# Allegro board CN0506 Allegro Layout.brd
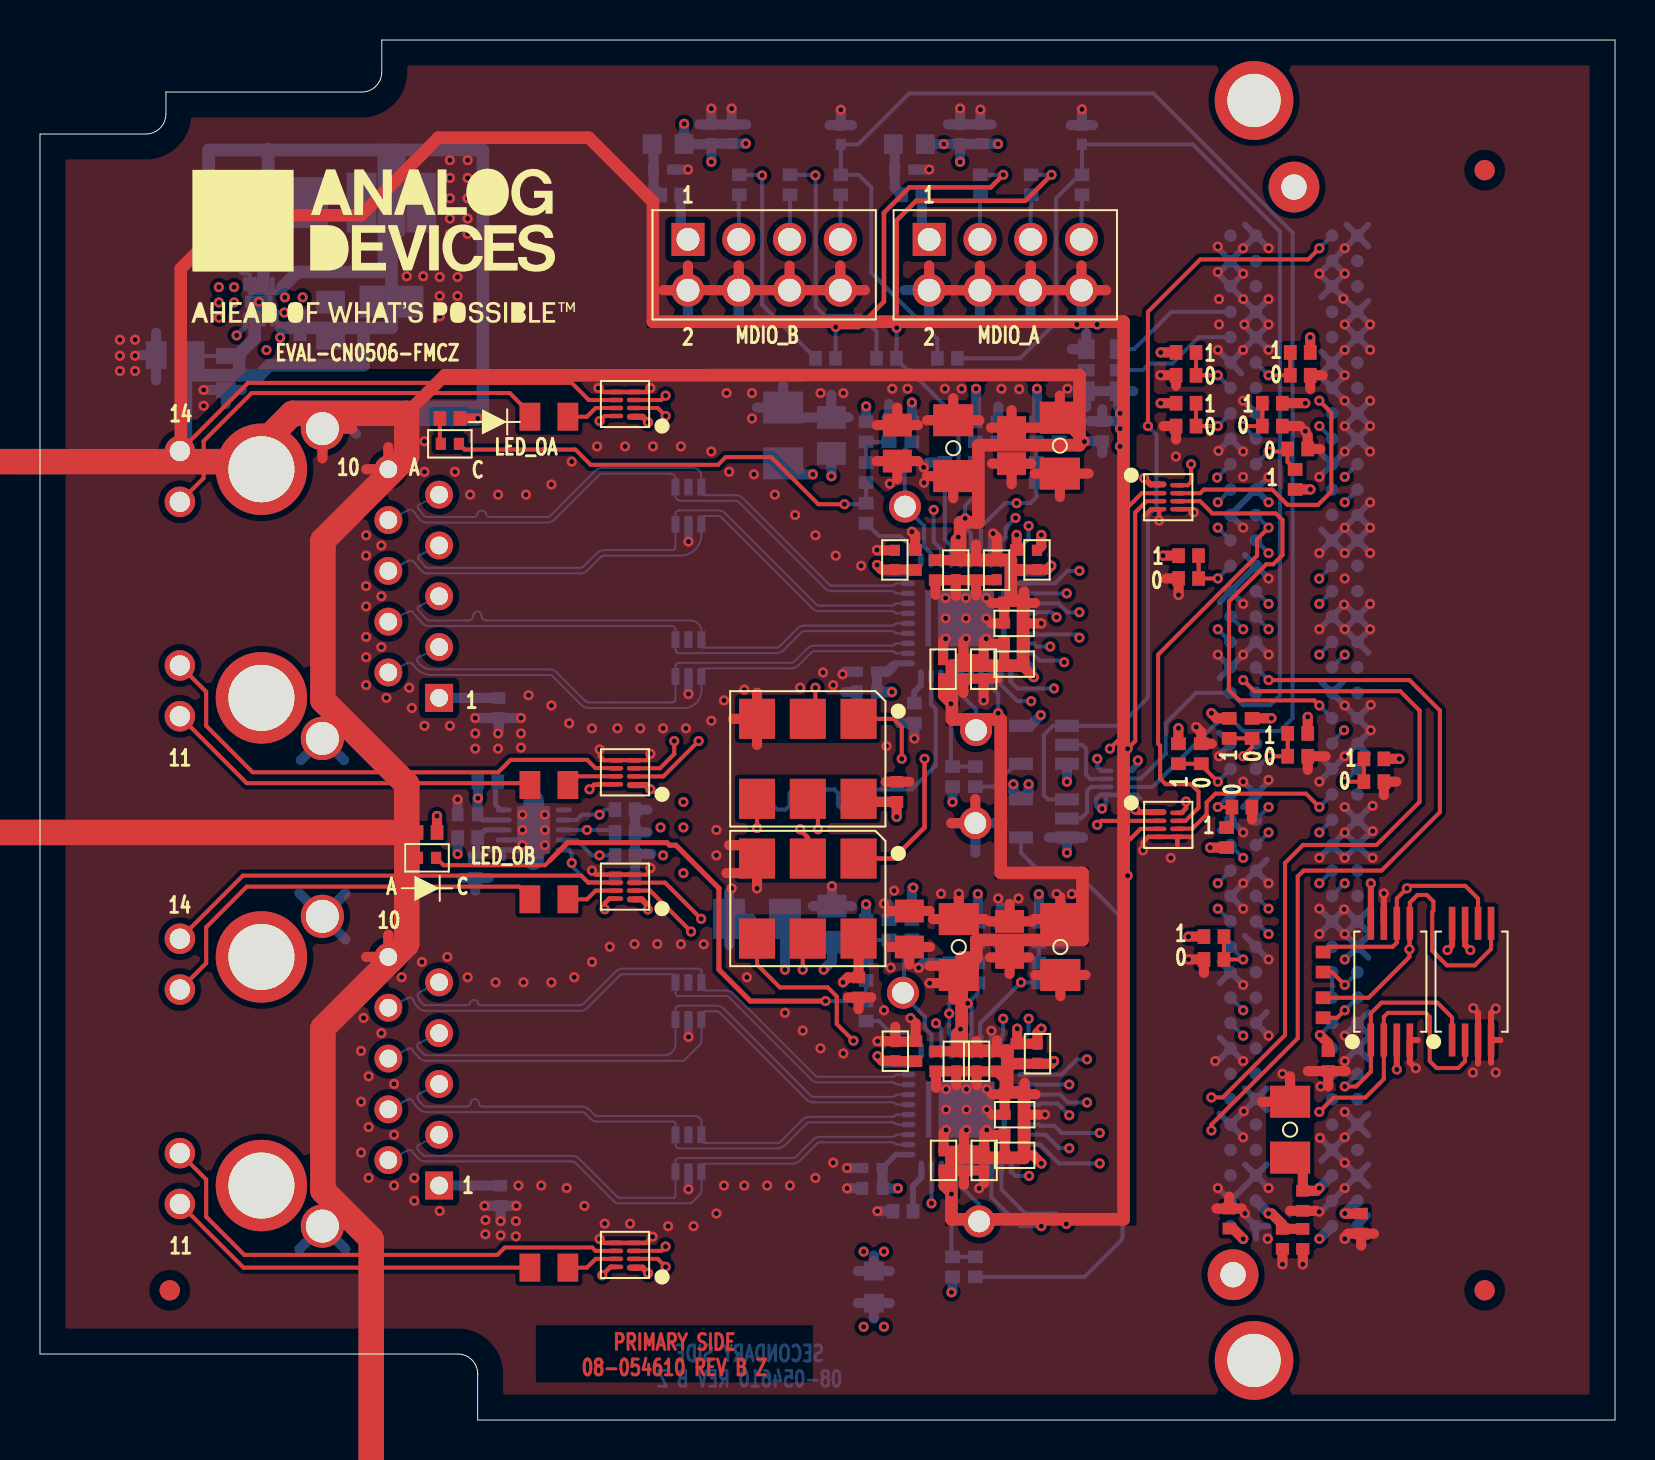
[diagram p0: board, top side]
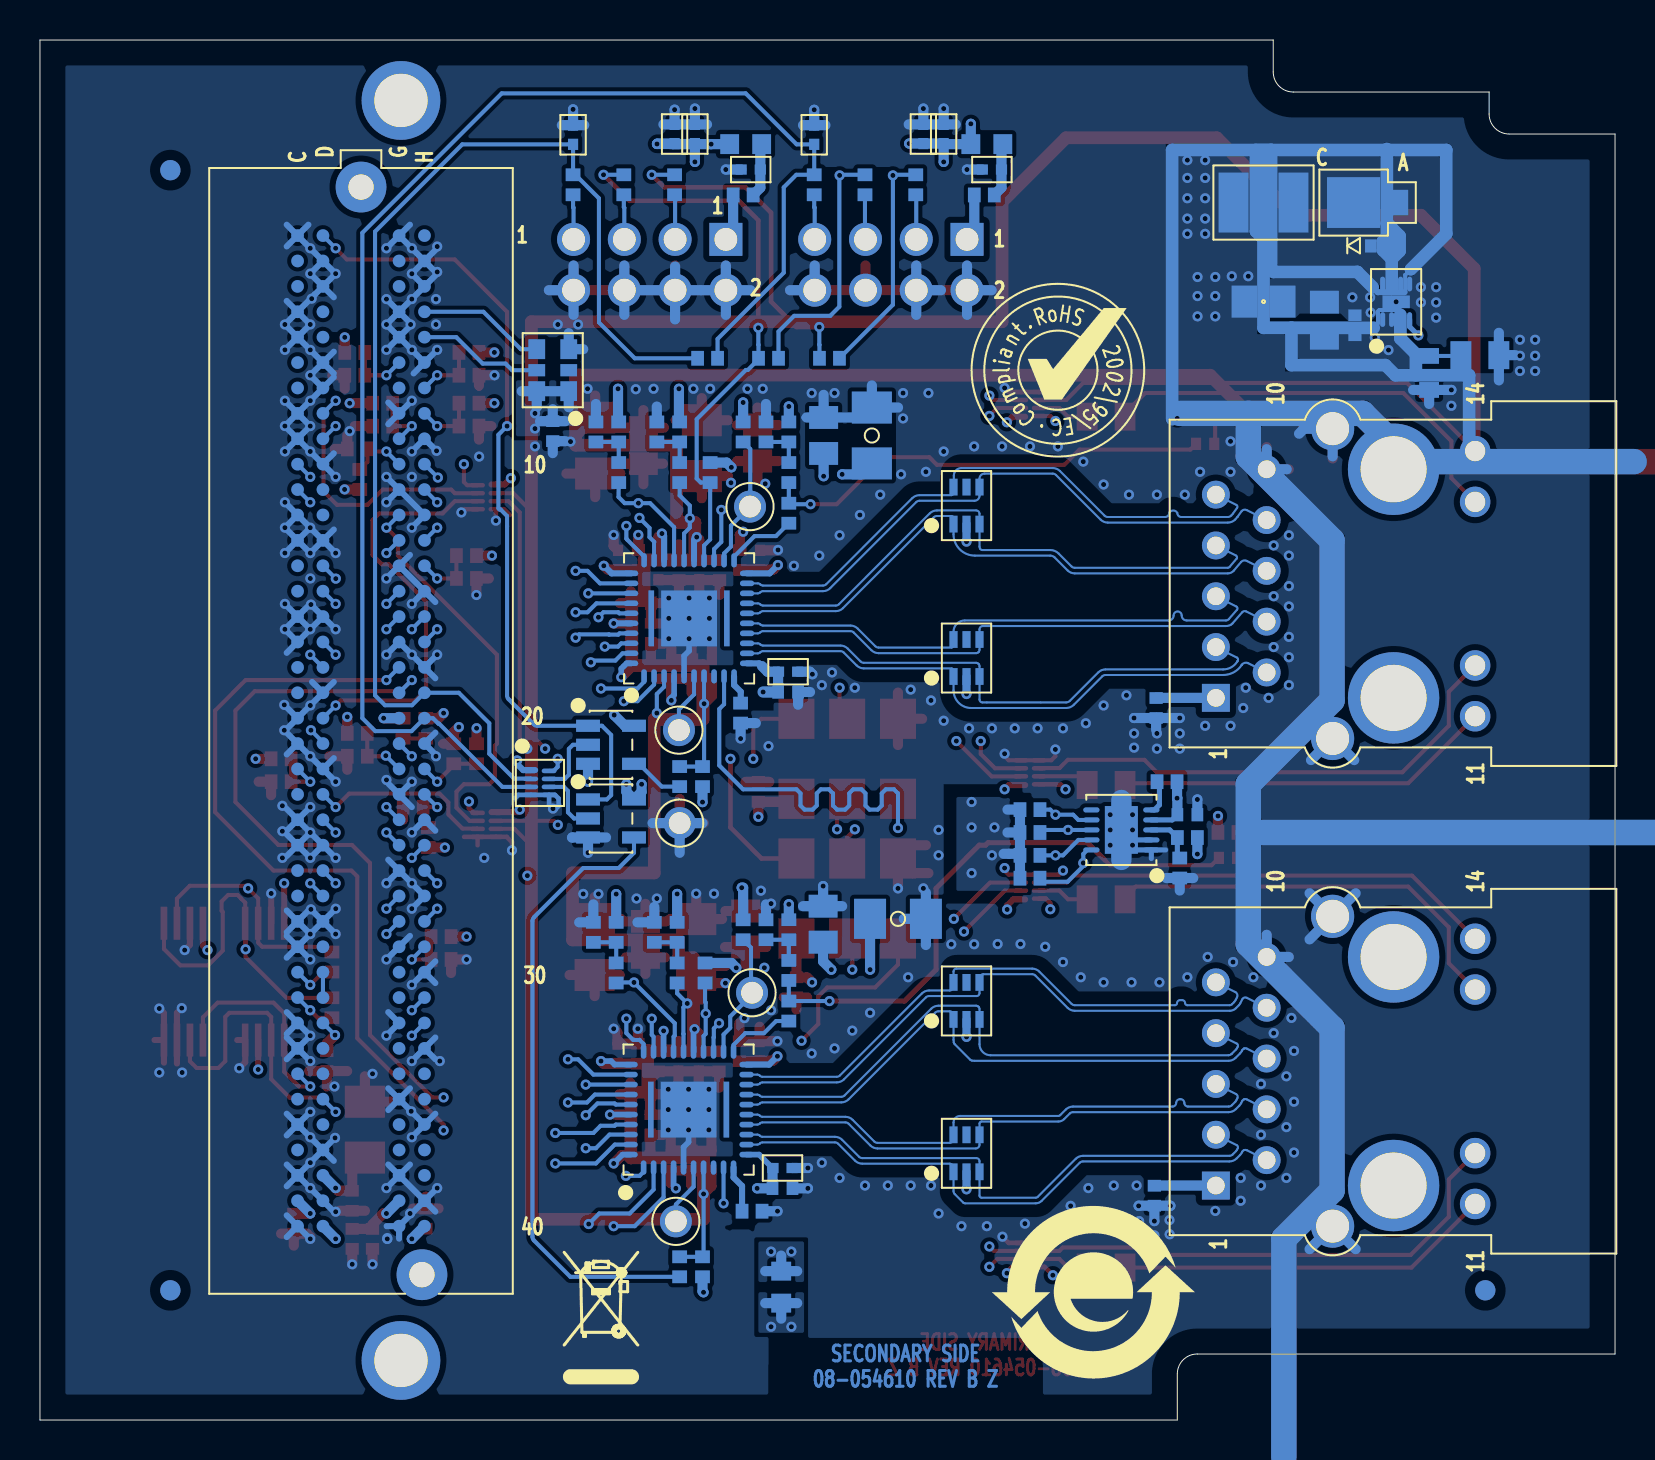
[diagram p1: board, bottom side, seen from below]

Outline 78.8 x 69 mm; copper layers: TOP, L2_GND, L3_SIG, L4_GND, L5_PWR, L6_SIG, L7_GND, BOTTOM. Coordinates in mm from the lower left corner of the outline.
Outline path: 0,64.3 0,3.3 20.9,3.3 arc(21.61,3.01) 21.9,2.3 21.9,0 78.8,0 78.8,69 17.1,69 17.1,67.4 arc(16.81,66.69) 16.1,66.4 6.3,66.4 6.3,65.3 arc(6.01,64.59) 5.3,64.3 0,64.3

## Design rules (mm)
constraint set DEFAULT: min track width 0.203
net group MDI_0A: nets MDI_0A_N MDI_0A_P
net group MDI_0B: nets MDI_0B_N MDI_0B_P
net group MDI_1A: nets MDI_1A_N MDI_1A_P
net group MDI_1B: nets MDI_1B_N MDI_1B_P
net group MDI_2A: nets MDI_2A_N MDI_2A_P
net group MDI_2B: nets MDI_2B_N MDI_2B_P
net group MDI_3A: nets MDI_3A_N MDI_3A_P
net group MDI_3B: nets MDI_3B_N MDI_3B_P
net group XTAL: nets XTAL_I_A XTAL_I_B
net group RX_A: nets RX_CTL/RX_DV_A RXC/RX_CLK_A RXD_0A RXD_1A RXD_2A RXD_3A
net group RX_B: nets RX_CTL/RX_DV_B RXC/RX_CLK_B RXD_0B RXD_1B RXD_2B RXD_3B
net group TX_A: nets TX_CTL/TX_EN_A TXC/TX_CLK_A TXD_0A TXD_1A TXD_2A TXD_3A
net group TX_B: nets TX_CTL/TX_EN_B TXC/TX_CLK_B TXD_0B TXD_1B TXD_2B TXD_3B

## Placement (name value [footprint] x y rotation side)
C1  0.1UF  [C0402]  46.2 37.54 90 top
C2  0.01UF  [C0402H22]  47.21 37.54 90 top
C3  0.01UF  [C0402H22]  45.18 37.54 90 top
C4  0.01UF  [C0402H22]  49.88 43 90 top
C5  0.1UF  [C0402]  48.86 43 90 top
C6  0.1UF  [C0402]  41.37 36.4 180 bottom
C7  0.01UF  [C0402H22]  41.37 37.42 180 bottom
C8  0.1UF  [C0402]  43.78 43 90 top
C9  0.01UF  [C0402H22]  42.77 43 90 top
C10  0.1UF  [C0402]  48.74 40.84 180 top
C11  0.01UF  [C0402H22]  48.74 39.83 180 top
C12  0.1UF  [C0402]  44.8 42.5 270 top
C13  0.01UF  [C0402H22]  48.74 37.8 180 top
C14  1uF  [C0805]  48.61 48.72 90 top
C15  4.7uF  [C1206H71]  51.02 48.72 270 top
C16  1uF  [C0805]  39.59 49.23 90 bottom
C17  4.7uF  [C1206H71]  37.18 49.23 270 bottom
C18  1uF  [C0805]  43.49 24.55 90 top
C19  4.7uF  [C1206H71]  45.97 23.65 270 top
C20  0.1UF  [C0402]  48.74 38.81 180 top
C21  0.01UF  [C0402H22]  45.82 42.5 270 top
C22  0.1UF  [C0402]  46.83 42.5 270 top
C23  0.01UF  [C0402H22]  47.86 42.49 270 top
C24  0.1UF  [C0402]  42.86 31.41 90 top
C25  0.1UF  [C0402]  40.95 21.63 270 top
C26  0.1UF  [C0402]  22.96 35.6 90 bottom
C27  0.1UF  [C0402]  21.4 30.27 180 bottom
C34  0.1UF  [C0402]  23.05 11.22 90 bottom
C36  0.1UF  [C0402]  13.01 54.74 90 bottom
C37  1uF  [C0805]  14.54 54.99 90 bottom
C38  0.1UF  [C0402]  11.71 58.7 0 bottom
C39  47uF  [C0805H60]  17.59 55.92 0 bottom
C40  0.01UF  [C0402H22]  43.24 62.52 0 bottom
C41  0.01UF  [C0402H22]  46.03 64.3 90 bottom
C42  0.01UF  [C0402H22]  52.13 64.26 90 bottom
C43  0.01UF  [C0402H22]  47.05 64.3 90 bottom
C44  0.01UF  [C0402H22]  31.17 62.52 0 bottom
C45  0.01UF  [C0402H22]  33.59 64.3 90 bottom
C46  0.01UF  [C0402H22]  40.06 64.26 90 bottom
C47  0.01UF  [C0402H22]  34.6 64.3 90 bottom
C48  0.1UF  [C0402]  46.22 12.98 90 top
C49  0.01UF  [C0402H22]  47.24 12.98 90 top
C50  0.01UF  [C0402H22]  45.21 12.98 90 top
C51  0.01UF  [C0402H22]  48.76 13.23 180 top
C52  0.1UF  [C0402]  48.76 14.25 180 top
C53  0.1UF  [C0402]  41.65 11.58 180 bottom
C54  0.01UF  [C0402H22]  41.65 12.6 180 bottom
C55  0.1UF  [C0402]  43.81 18.44 90 top
C56  0.01UF  [C0402H22]  42.79 18.44 90 top
C57  0.1UF  [C0402]  48.76 16.28 180 top
C58  0.01UF  [C0402H22]  48.76 15.27 180 top
C59  0.1UF  [C0402]  48.89 18.31 90 top
C60  0.01UF  [C0402H22]  49.91 18.31 90 top
C61  1uF  [C0805]  48.51 24.03 90 top
C62  4.7uF  [C1206H71]  51.05 23.65 270 top
C63  1uF  [C0805]  39.62 24.79 90 bottom
C64  4.7uF  [C1206H71]  35.87 25.06 0 bottom
C65  1uF  [C0805]  42.9 48.85 90 top
C66  0.1UF  [C0402]  44.83 17.93 270 top
C67  4.7uF  [C1206H71]  45.69 48.59 270 top
C68  0.01UF  [C0402H22]  45.84 17.93 270 top
C69  0.1UF  [C0402]  47.87 17.93 270 top
C70  0.01UF  [C0402H22]  46.86 17.93 270 top
C73  0.1UF  [C0402]  53.15 49.44 270 bottom
C74  0.1UF  [C0402]  59.5 10.07 90 top
C75  0.1UF  [C0402]  63.18 9.06 270 top
C76  0.1UF  [C0402]  62.16 9.06 270 top
C77  4.7uF  [C1206H71]  62.54 14.52 90 top
C78  0.1UF  [C0402]  64.45 17.95 270 top
C79  0.1UF  [C0402]  63.18 10.96 270 top
C83  0.1UF  [C0402]  66.1 9.82 270 top
CLK25A  1405-2  [CNKEY1405-2]  46.83 34.49 180 bottom
CLK25B  1405-2  [CNKEY1405-2]  46.99 9.93 180 bottom
D1  SP3001-04JTG  [SC70-6H43]  32.44 38.1 180 bottom
D2  SP3001-04JTG  [SC70-6H43]  32.44 45.72 180 bottom
D3  MBRM140T1G  [DO216]  12.38 60.87 180 bottom
D4  SP3001-04JTG  [SC70-6H43]  32.44 13.33 180 bottom
D5  SP3001-04JTG  [SC70-6H43]  32.44 20.95 180 bottom
DS2  SML-P11MTT86RR  [LED0402]  19.36 28.11 180 top
DS4  SML-P11MTT86RR  [LED0402]  20.51 48.81 180 top
E1  220OHMS  [L0603]  41.72 6.64 270 bottom
L1  3.3UH  [L1812H110]  17.59 60.87 0 bottom
L2  10nH  [L0603]  43.49 63.79 0 bottom
L3  10nH  [L0603]  31.43 63.79 0 bottom
M1  7499111446  [MWURTH7499111446]  19.97 11.72 90 bottom
M2  7499111446  [MWURTH7499111446]  19.97 36.11 90 bottom
NOREF  -  []  0 3.3 0 top
NOREF#2  -  []  0 3.3 0 top
NOREF#3  -  []  78.8 0 0 top
NOREF#4  -  [unnamed#2]  60.74 65.98 0 top
NOREF#5  -  []  21.67 2.94 0 top
NOREF#6  -  []  0 64.3 0 top
NOREF#7  -  []  6.13 64.75 0 top
NOREF#8  -  []  16.9 66.8 0 top
NOREF#9  -  []  21.9 0 0 top
NOREF#10  -  []  0.24 235.41 0 top
NOREF#11  -  []  37.4 2.71 270 top
NOREF#12  -  []  21.9 0 0 top
NOREF#13  -  []  0 64.3 0 top
NOREF#14  -  [unnamed#2]  72.28 62.49 0 top
NOREF#15  -  []  78.8 0 90 top
NOREF#16  -  []  7 10.8 0 top
NOREF#17  -  []  3.23 268 0 top
NOREF#18  -  []  7 10.8 0 top
NOREF#19  -  []  6.3 66.4 0 top
NOREF#20  -  []  6.3 66.4 0 top
NOREF#21  -  []  17.1 69 0 top
NOREF#22  -  [unnamed#2]  60.74 2.98 0 top
NOREF#23  -  []  -16.73 330.71 0 top
NOREF#24  -  []  -67.78 -61.39 0 top
NOREF#25  -  []  17.1 69 0 top
NOREF#26  -  []  41.94 89.11 0 top
NOREF#27  -  [unnamed#2]  6.49 6.49 0 top
NOREF#28  -  []  9.97 117.47 0 top
NOREF#29  -  []  -67.78 -61.39 0 top
NOREF#30  -  []  -67.78 -61.39 0 top
NOREF#31  -  []  17.19 58.69 0 top
NOREF#32  -  [unnamed#2]  72.28 6.49 0 top
NOREF#33  -  []  27.87 52.49 180 bottom
NOREF#34  -  []  26.09 6.39 180 bottom
NOREF#35  -  [unnamed#2]  72.28 62.49 180 bottom
NOREF#36  -  []  50.93 1.84 180 bottom
NOREF#37  -  [unnamed#2]  6.49 6.49 180 bottom
NOREF#38  -  [unnamed#2]  72.28 6.49 180 bottom
P2  SSQ-104-01-T-D  [CNTHFHDR2X4L420W195H340]  32.42 59.03 0 top
P3  1405-2  [CNKEY1405-2]  46.8 29.84 0 bottom
P4  1405-2  [CNKEY1405-2]  43.28 45.67 180 bottom
P6  SSQ-104-01-T-D  [CNTHFHDR2X4L420W195H340]  44.48 59.03 0 top
P7  1405-2  [CNKEY1405-2]  43.18 21.36 180 bottom
P8  ASP-134604-01  [CNSAMTECASP-134604-01]  62.74 34.46 270 bottom
R1  0  [R0402]  46.8 32.17 90 bottom
R2  1K  [R0402]  45.65 32.17 90 bottom
R3  3.01K  [R0402]  43.75 35.35 90 bottom
R4  0  [R0402]  41.33 45.34 90 bottom
R5  1.5K  [R0402]  45.27 47.37 270 bottom
R6  1.5K  [R0402]  43.62 49.4 270 bottom
R7  25  [R0402]  64.19 22.9 270 top
R8  10K  [R0402]  63.05 53.38 180 top
R9  10K  [R0402]  63.05 52.24 0 top
R10  25  [R0402]  64.19 20.61 270 top
R11  10K  [R0402]  57.46 43.22 0 top
R12  10K  [R0402]  57.46 42.08 180 top
R13  10K  [R0402]  29.27 27.09 180 bottom
R14  10K  [R0402]  62.8 47.03 90 top
R15  10K  [R0402]  62.92 48.55 0 top
R16  10K  [R0402]  61.65 50.84 180 top
R17  10K  [R0402]  61.65 49.7 0 top
R18  10K  [R0402]  57.34 50.84 0 top
R19  10K  [R0402]  57.34 49.7 180 top
R20  10K  [R0402]  57.34 53.38 0 top
R21  10K  [R0402]  57.34 52.24 180 top
R22  150  [R0805]  25.46 7.62 180 top
R23  150  [R0805]  25.46 26.03 180 top
R24  150  [R0805]  25.46 31.75 180 top
R25  150  [R0805]  25.46 50.16 180 top
R26  10K  [R0402]  22.41 31.92 0 bottom
R27  102K  [R0402]  21.78 27.6 270 bottom
R28  3K  [R0402]  19.36 29.38 0 top
R29  0  [R0402]  49.84 47.37 90 bottom
R30  0  [R0402]  49.97 22.35 90 bottom
R31  10K  [R0402]  49.84 49.4 270 bottom
R32  56K  [R0402]  50.99 49.4 90 bottom
R33  10K  [R0402]  49.97 24.38 270 bottom
R34  56K  [R0402]  51.11 24.38 90 bottom
R35  0  [R0402]  46.8 47.37 90 bottom
R36  0  [R0402]  46.92 22.35 90 bottom
R37  10K  [R0402]  46.8 49.4 270 bottom
R38  10K  [R0402]  47.94 49.4 90 bottom
R39  10K  [R0402]  46.92 24.38 270 bottom
R40  10K  [R0402]  48.07 24.38 90 bottom
R41  0  [R0402]  41.33 22.48 90 bottom
R42  0  [R0402]  41.33 47.37 90 bottom
R43  10K  [R0402]  41.33 24.51 270 bottom
R44  10K  [R0402]  42.48 24.51 90 bottom
R45  10K  [R0402]  41.33 49.4 270 bottom
R46  10K  [R0402]  42.48 49.4 90 bottom
R47  10K  [R0402]  29.27 28.23 0 bottom
R48  976K  [R0402]  21.4 29.12 0 bottom
R49  10K  [R0402]  29.27 29.38 0 bottom
R53  3K  [R0402]  20.51 50.08 0 top
R54  100K  [R0805]  6.76 53.24 0 bottom
R55  12.4K  [R0603]  9.3 52.35 270 bottom
R56  0  [R0402]  39.3 53.09 180 bottom
R57  0  [R0402]  42.35 53.09 180 bottom
R58  0  [R0402]  45.4 53.09 180 bottom
R59  0  [R0402]  43.62 61.25 180 bottom
R60  0  [R0402]  52.13 61.76 90 bottom
R61  0  [R0402]  47.05 61.76 90 bottom
R62  0  [R0402]  49.59 61.76 90 bottom
R63  0  [R0402]  31.56 61.25 180 bottom
R64  0  [R0402]  40.06 61.76 90 bottom
R65  0  [R0402]  34.98 61.76 90 bottom
R66  0  [R0402]  37.52 61.76 90 bottom
R67  0  [R0402]  46.8 7.66 90 bottom
R68  1K  [R0402]  45.65 7.66 90 bottom
R69  3.01K  [R0402]  43.18 10.44 0 bottom
R70  0  [R0402]  41.33 20.45 90 bottom
R71  1.5K  [R0402]  45.53 22.35 270 bottom
R72  1.5K  [R0402]  43.62 24.51 270 bottom
R74  10K  [R0402]  66.73 33.06 180 top
R75  10K  [R0402]  66.73 31.92 0 top
R76  10K  [R0402]  29.27 30.52 180 bottom
R77  10K  [R0402]  58.73 24.17 0 top
R78  10K  [R0402]  58.73 23.03 180 top
R80  10K  [R0402]  62.92 34.33 180 top
R81  10K  [R0402]  62.92 33.19 0 top
R82  10K  [R0402]  59.5 34.58 270 top
R83  10K  [R0402]  60.64 34.58 90 top
R84  10K  [R0402]  59.37 29.12 90 top
R85  10K  [R0402]  60.13 30.65 0 top
R86  10K  [R0402]  56.96 33.31 270 top
R87  10K  [R0402]  58.1 33.31 90 top
U1  ADIN1300CCPZ  [QFN40_6X6_3PAD]  46.35 15.52 180 bottom
U2  ADIN1300CCPZ  [QFN40_6X6_3PAD]  46.32 40.08 180 bottom
U3  NLSV2T240MUTAG  [DFN8_1_8X1_2]  53.79 31.86 270 bottom
U4  LT3502AEDC#TRMPBF  [DFN8_2X2_PAD1_37X0_64]  10.95 55.91 180 bottom
U5  SN74AHC1G09DBVR  [SOT23-5L-2]  50.23 33.76 270 bottom
U6  SN74AHC1G09DBVR  [SOT23-5L-2]  50.23 30.08 270 bottom
U7  M24C02-RDW6TP  [TSSOP8]  67.56 21.92 0 top
U8  M24C02-RDW6TP  [TSSOP8]  71.62 21.92 0 top
U9  NLSV2T240MUTAG  [DFN8_1_8X1_2]  56.45 29.76 270 top
U10  NLSV2T240MUTAG  [DFN8_1_8X1_2]  29.27 8.25 90 top
U11  NLSV2T240MUTAG  [DFN8_1_8X1_2]  29.27 26.67 90 top
U12  NLSV2T240MUTAG  [DFN8_1_8X1_2]  29.27 32.38 90 top
U13  NLSV2T240MUTAG  [DFN8_1_8X1_2]  29.27 50.8 90 top
U14  NLSV2T240MUTAG  [DFN8_1_8X1_2]  56.45 46.14 270 top
U15  LTC4316IDD#PBF  [QFN10_3X3_PAD2_38X1_64]  24.7 29.5 90 bottom
Y1  25MEGHZ  [YSML276W197H71]  38.41 33.06 180 top
Y2  25MEGHZ  [YSML276W197H71]  38.41 26.07 180 top
Y3  125.0000MEGHZ  [DFN6_3_2X2_5]  53.15 52.49 90 bottom

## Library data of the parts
C1 C5 C6 C8 C10 C12 C20 C22 C24-C27 C34 C36 C38 C48 C52 C53 C55 C57 C59 C66 C69 C73-C76 C78 C79 C83 = CAP: User Part Number: UPN; Tolerance: 10; alternate symbols: (C0402L_ALT); part number: CAP_SM-0.1UF,50V,10,E026461,C0402; tolerance: 10
C2-C4 C7 C9 C11 C13 C21 C23 C40-C47 C49-C51 C54 C56 C58 C60 C68 C70 = CAP: Tolerance: 10; User Part Number: UPN; alternate symbols: (); part number: CAP_SM-0.01UF,25V,10,E029190,C0402H22; tolerance: 10
C14 C16 C18 C37 C61 C63 C65 = CAP: User Part Number: UPN; Tolerance: 10; alternate symbols: (); part number: CAP_SM-1UF,100V,10,E014208,C0805; tolerance: 10
C15 C17 C19 C62 C64 C67 C77 = CAP: Tolerance: 10; User Part Number: UPN; alternate symbols: (); part number: CAP_SM-4.7UF,25V,10,E018868,C1206H71; tolerance: 10
C39 = CAP: Tolerance: 20; User Part Number: UPN; alternate symbols: (C0805L); part number: CAP_SM-47UF,6.3V,20,E008247,C0805H60; tolerance: 20
CLK25A CLK25B P3 P4 P7 = CN1P: Tolerance: N/A; User Part Number: UPN; alternate symbols: (); part number: CN1P_TH-1405-2,E022242,CNKEY1405-2; tolerance: N/A
D1 D2 D4 D5 = DIOTVS6P_V2: User Part Number: UPN; Tolerance: N/A; alternate symbols: (); part number: DIOTVS6P_V2_SM-SP3001-04JTG,6V,N/A,E035886,SC70-6H43; tolerance: N/A
D3 = DIOSCHOTTKY: Tolerance: N/A; User Part Number: UPN; alternate symbols: (); part number: DIOSCHOTTKY_SM-MBRM140T1G,40V,N/A,E012399,DO216; tolerance: N/A
DS2 DS4 = DIOLED: User Part Number: UPN; Tolerance: N/A; alternate symbols: (); part number: DIOLED_SM-SML-P11MTT86R,N/A,N/A,E014445,LED0402; tolerance: N/A
E1 = FERRITE: User Part Number: UPN; Tolerance: 25; alternate symbols: (); part number: FERRITE_SM-220OHMS,25,E007178,L0603; tolerance: 25
L1 = IND: User Part Number: UPN; Tolerance: N/A; alternate symbols: (); part number: IND_SM-3.3UH,N/A,E035063,L1812H110; tolerance: N/A
L2 L3 = IND: User Part Number: UPN; Tolerance: 2; alternate symbols: (L0603L); part number: IND_SM-10NH,2,E016777,L0603; tolerance: 2
M1 M2 = MOD_7499111446: User Part Number: UPN; Tolerance: N/A; alternate symbols: (); part number: MOD_7499111446_TH-7499111446,E032187,MWURTH7499111446; tolerance: N/A
P2 P6 = CN8P_ODD_EVEN_V2: User Part Number: UPN; Tolerance: N/A; alternate symbols: (); part number: CN8P_ODD_EVEN_V2_TH-SSQ-104-01-T-D,E028951,CNTHFHDR2X4L420W195H340; tolerance: N/A
P8 = CN160P_CDGH: User Part Number: UPN; Tolerance: N/A; alternate symbols: (CNSAMTECASP-134604-01_KITTRF,CNSAMTECASP-134604-01_EVKP); part number: CN160P_CDGH_SM-ASP-134604-01,E011383,CNSAMTECASP-134604-01; tolerance: N/A
R1 R4 R29 R30 R35 R36 R41 R42 R56-R67 R70 = RES: User Part Number: UPN; Tolerance: 5; alternate symbols: (R0402L,R0402L_ALT); part number: RES_SM-0,E003438,N/A,5,R0402; tolerance: 5
R2 R68 = RES: User Part Number: UPN; Tolerance: 1; alternate symbols: (R0402L,R0402L_ALT); part number: RES_SM-1K,E003763,1/10W,1,R0402; tolerance: 1
R3 R69 = RES: User Part Number: UPN; Tolerance: 1; alternate symbols: (R0402L); part number: RES_SM-3.01K,E027299,1/10W,1,R0402; tolerance: 1
R5 R6 R71 R72 = RES: User Part Number: UPN; Tolerance: 1; alternate symbols: (R0402L); part number: RES_SM-1.5K,E003782,1/10W,1,R0402; tolerance: 1
R7 R10 = RES: User Part Number: UPN; Tolerance: 0.1; alternate symbols: (R0402L); part number: RES_SM-25,E030344,1/20,0.1,R0402; tolerance: 0.1
R8 R9 R11-R21 R26 R31 R33 R37-R40 R43-R47 R49 R74-R78 R80-R87 = RES: User Part Number: UPN; Tolerance: 1; alternate symbols: (R0402L,R0402L_ALT); part number: RES_SM-10K,E003751,1/10W,1,R0402; tolerance: 1
R22-R25 = RES: User Part Number: UPN; Tolerance: 1; alternate symbols: (R0805L); part number: RES_SM-150,E003413,1/8W,1,R0805; tolerance: 1
R27 = RES: User Part Number: UPN; Tolerance: 1; alternate symbols: (R0402L); part number: RES_SM-102K,E020517,1/10W,1,R0402; tolerance: 1
R28 R53 = RES: User Part Number: UPN; Tolerance: 5; alternate symbols: (R0402L); part number: RES_SM-3K,E008023,1/16W,5,R0402; tolerance: 5
R32 R34 = RES: User Part Number: UPN; Tolerance: 1; alternate symbols: (R0402L); part number: RES_SM-56K,E017978,1/10W,1,R0402; tolerance: 1
R48 = RES: User Part Number: UPN; Tolerance: 1; alternate symbols: (R0402L); part number: RES_SM-976K,E026630,1/16W,1,R0402; tolerance: 1
R54 = RES: User Part Number: UPN; Tolerance: 1; alternate symbols: (R0805L); part number: RES_SM-100K,E003488,1/8W,1,R0805; tolerance: 1
R55 = RES: User Part Number: UPN; Tolerance: 1; alternate symbols: (R0603L); part number: RES_SM-12.4K,E015341,1/10W,1,R0603; tolerance: 1
U1 U2 = ADIN1300: User Part Number: UPN; Tolerance: N/A; alternate symbols: (); part number: ADIN1300_SM-ADIN1300CCPZ,E032258,QFN40_6X6_3PAD; tolerance: N/A
U3 U9-U14 = ICNLSV2T240: User Part Number: UPN; Tolerance: N/A; alternate symbols: (); part number: ICNLSV2T240_SM-NLSV2T240MUTAG,E034983,DFN8_1_8X1_2; tolerance: N/A
U4 = ADLT3502: User Part Number: UPN; Tolerance: N/A; alternate symbols: (); part number: ADLT3502_SM-LT3502AEDC#TRMPBF,E035029,DFN8_2X2_PAD1_37X0_64; tolerance: N/A
U5 U6 = 74109_V2: User Part Number: UPN; Tolerance: N/A; alternate symbols: (); part number: 74109_V2_SM-SN74AHC1G09DBVR,E034982,SOT23-5L-2; tolerance: N/A
U7 U8 = ICM24CXX: Tolerance: N/A; User Part Number: UPN; alternate symbols: (); part number: ICM24CXX_SM-M24C02-RDW6TP,E027045,TSSOP8; tolerance: N/A
U15 = ADLTC4316: User Part Number: UPN; Tolerance: N/A; alternate symbols: (); part number: ADLTC4316_SM-LTC4316IDD#PBF,E028272,QFN10_3X3_PAD2_38X1_64; tolerance: N/A
Y1 Y2 = XTALOSC6P_V27: Tolerance: N/A; User Part Number: UPN; alternate symbols: (); part number: XTALOSC6P_V27_SM-25MEGHZ,E040522,YSML276W197H71; tolerance: N/A
Y3 = XTALOSC6P_V24: User Part Number: UPN; Tolerance: N/A; alternate symbols: (); part number: XTALOSC6P_V24_SM-125.0000MEGHZ,E035031,DFN6_3_2X2_5; tolerance: N/A

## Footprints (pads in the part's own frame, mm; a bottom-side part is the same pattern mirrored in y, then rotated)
C0402
  rect 0.584x0.66 smd: 1(-0.5,0) 2(0.5,0)
C0402H22
  rect 0.559x0.508 smd: 1(-0.479,0) 2(0.479,0)
C0805
  rect 1.143x1.448 smd: 1(-0.9,0) 2(0.9,0)
C0805H60
  rect 1.295x1.6 smd: 1(-0.953,0) 2(0.953,0)
C1206H71
  rect 1.6x2.007 smd: 1(-1.397,0) 2(1.397,0)
CNKEY1405-2
  round 1.6 hole 1.092: 1(0,0)
CNSAMTECASP-134604-01
  round 2.54 hole 1.27 unplated: (-27.191,0) (27.191,3.048)
  round 0.635 smd: C1(-24.765,-3.175) C2(-23.495,-3.175) C3(-22.225,-3.175) C4(-20.955,-3.175) C5(-19.685,-3.175) C6(-18.415,-3.175) C7(-17.145,-3.175) C8(-15.875,-3.175) C9(-14.605,-3.175) C10(-13.335,-3.175) C11(-12.065,-3.175) C12(-10.795,-3.175) C13(-9.525,-3.175) C14(-8.255,-3.175) C15(-6.985,-3.175) C16(-5.715,-3.175) C17(-4.445,-3.175) C18(-3.175,-3.175) C19(-1.905,-3.175) C20(-0.635,-3.175) C21(0.635,-3.175) C22(1.905,-3.175) C23(3.175,-3.175) C24(4.445,-3.175) C25(5.715,-3.175) C26(6.985,-3.175) C27(8.255,-3.175) C28(9.525,-3.175) C29(10.795,-3.175) C30(12.065,-3.175) C31(13.335,-3.175) C32(14.605,-3.175) C33(15.875,-3.175) C34(17.145,-3.175) C35(18.415,-3.175) C36(19.685,-3.175) C37(20.955,-3.175) C38(22.225,-3.175) C39(23.495,-3.175) C40(24.765,-3.175) D1(-24.765,-1.905) D2(-23.495,-1.905) D3(-22.225,-1.905) D4(-20.955,-1.905) D5(-19.685,-1.905) D6(-18.415,-1.905) D7(-17.145,-1.905) D8(-15.875,-1.905) D9(-14.605,-1.905) D10(-13.335,-1.905) D11(-12.065,-1.905) D12(-10.795,-1.905) D13(-9.525,-1.905) D14(-8.255,-1.905) D15(-6.985,-1.905) D16(-5.715,-1.905) D17(-4.445,-1.905) D18(-3.175,-1.905) D19(-1.905,-1.905) D20(-0.635,-1.905) D21(0.635,-1.905) D22(1.905,-1.905) D23(3.175,-1.905) D24(4.445,-1.905) D25(5.715,-1.905) D26(6.985,-1.905) D27(8.255,-1.905) D28(9.525,-1.905) D29(10.795,-1.905) D30(12.065,-1.905) D31(13.335,-1.905) D32(14.605,-1.905) D33(15.875,-1.905) D34(17.145,-1.905) D35(18.415,-1.905) D36(19.685,-1.905) D37(20.955,-1.905) D38(22.225,-1.905) D39(23.495,-1.905) D40(24.765,-1.905) G1(-24.765,1.905) G2(-23.495,1.905) G3(-22.225,1.905) G4(-20.955,1.905) G5(-19.685,1.905) G6(-18.415,1.905) G7(-17.145,1.905) G8(-15.875,1.905) G9(-14.605,1.905) G10(-13.335,1.905) G11(-12.065,1.905) G12(-10.795,1.905) G13(-9.525,1.905) G14(-8.255,1.905) G15(-6.985,1.905) G16(-5.715,1.905) G17(-4.445,1.905) G18(-3.175,1.905) G19(-1.905,1.905) G20(-0.635,1.905) G21(0.635,1.905) G22(1.905,1.905) G23(3.175,1.905) G24(4.445,1.905) G25(5.715,1.905) G26(6.985,1.905) G27(8.255,1.905) G28(9.525,1.905) G29(10.795,1.905) G30(12.065,1.905) G31(13.335,1.905) G32(14.605,1.905) G33(15.875,1.905) G34(17.145,1.905) G35(18.415,1.905) G36(19.685,1.905) G37(20.955,1.905) G38(22.225,1.905) G39(23.495,1.905) G40(24.765,1.905) H1(-24.765,3.175) H2(-23.495,3.175) H3(-22.225,3.175) H4(-20.955,3.175) H5(-19.685,3.175) H6(-18.415,3.175) H7(-17.145,3.175) H8(-15.875,3.175) H9(-14.605,3.175) H10(-13.335,3.175) H11(-12.065,3.175) H12(-10.795,3.175) H13(-9.525,3.175) H14(-8.255,3.175) H15(-6.985,3.175) H16(-5.715,3.175) H17(-4.445,3.175) H18(-3.175,3.175) H19(-1.905,3.175) H20(-0.635,3.175) H21(0.635,3.175) H22(1.905,3.175) H23(3.175,3.175) H24(4.445,3.175) H25(5.715,3.175) H26(6.985,3.175) H27(8.255,3.175) H28(9.525,3.175) H29(10.795,3.175) H30(12.065,3.175) H31(13.335,3.175) H32(14.605,3.175) H33(15.875,3.175) H34(17.145,3.175) H35(18.415,3.175) H36(19.685,3.175) H37(20.955,3.175) H38(22.225,3.175) H39(23.495,3.175) H40(24.765,3.175)
CNTHFHDR2X4L420W195H340
  rect 1.651x1.651 hole 1.143: 1(0,0)
  round 1.651 hole 1.143: 2(0,-2.54) 3(2.54,0) 4(2.54,-2.54) 5(5.08,0) 6(5.08,-2.54) 7(7.62,0) 8(7.62,-2.54)
DFN6_3_2X2_5
  rect 0.991x0.838 smd: 1(-1.05,-0.8) 3(1.05,-0.8) 4(1.05,0.8) 6(-1.05,0.8)
  rect 0.61x0.838 smd: 2(0,-0.8) 5(0,0.8)
DFN8_1_8X1_2
  oval 0.305x0.737 smd: 1(-0.638,-0.458)
  oval 0.229x0.737 smd: 2(-0.2,-0.458) 3(0.2,-0.458) 4(0.6,-0.458) 5(0.6,0.458) 6(0.2,0.458) 7(-0.2,0.458) 8(-0.6,0.458)
DFN8_2X2_PAD1_37X0_64
  oval 0.254x0.737 smd: 1(-0.675,-0.888) 2(-0.225,-0.888) 3(0.225,-0.888) 4(0.675,-0.888) 5(0.675,0.888) 6(0.225,0.888) 7(-0.225,0.888) 8(-0.675,0.888)
  rect 1.372x0.635 smd: PAD(0,0)
DO216
  rect 0.762x1.27 smd: A(1.651,0)
  rect 2.667x2.54 smd: C(-0.699,0)
L0603
  rect 0.94x0.991 smd: 1(-0.8,0) 2(0.8,0)
L1812H110
  rect 1.499x2.997 smd: 1(-1.499,0) 2(1.499,0)
LED0402
  rect 0.508x0.61 smd: A(0.454,0) C(-0.454,0)
MWURTH7499111446
  round 4.572 hole 3.302 unplated: (0,-8.89) (11.43,-8.89)
  rect 1.397x1.397 hole 0.889: 1(0,0)
  round 1.397 hole 0.889: 2(1.27,-2.54) 3(2.54,0) 4(3.81,-2.54) 5(5.08,0) 6(6.35,-2.54) 7(7.62,0) 8(8.89,-2.54) 9(10.16,0) 10(11.43,-2.54)
  round 1.524 hole 1.016: 11(-0.92,-12.97) 12(1.62,-12.97) 13(9.8,-12.97) 14(12.34,-12.97)
  round 2.159 hole 1.651: SH1(13.46,-5.84) SH2(-2.03,-5.84)
QFN10_3X3_PAD2_38X1_64
  oval 0.254x0.813 smd: 1(-1,-1.5) 2(-0.5,-1.5) 3(0,-1.5) 4(0.5,-1.5) 5(1,-1.5) 6(1,1.5) 7(0.5,1.5) 8(0,1.5) 9(-0.5,1.5) 10(-1,1.5)
  rect 2.388x1.651 smd: PAD(0,0)
QFN40_6X6_3PAD
  oval 0.279x0.711 smd: 1(-2.25,-2.901) 2(-1.75,-2.901) 3(-1.25,-2.901) 4(-0.75,-2.901) 5(-0.25,-2.901) 6(0.25,-2.901) 7(0.75,-2.901) 8(1.25,-2.901) 9(1.75,-2.901) 10(2.25,-2.901) 21(2.25,2.901) 22(1.75,2.901) 23(1.25,2.901) 24(0.75,2.901) 25(0.25,2.901) 26(-0.25,2.901) 27(-0.75,2.901) 28(-1.25,2.901) 29(-1.75,2.901) 30(-2.25,2.901)
  oval 0.711x0.279 smd: 11(2.901,-2.25) 12(2.901,-1.75) 13(2.901,-1.25) 14(2.901,-0.75) 15(2.901,-0.25) 16(2.901,0.25) 17(2.901,0.75) 18(2.901,1.25) 19(2.901,1.75) 20(2.901,2.25) 31(-2.901,2.25) 32(-2.901,1.75) 33(-2.901,1.25) 34(-2.901,0.75) 35(-2.901,0.25) 36(-2.901,-0.25) 37(-2.901,-0.75) 38(-2.901,-1.25) 39(-2.901,-1.75) 40(-2.901,-2.25)
  rect 0.279x2.794 smd: PAD1(-1.89,0) PAD3(1.89,0)
  rect 2.794x2.794 smd: PAD2(0,0)
R0402
  rect 0.635x0.737 smd: 1(-0.5,0) 2(0.5,0)
R0603
  rect 0.787x0.991 smd: 1(-0.85,0) 2(0.85,0)
R0805
  rect 1.041x1.397 smd: 1(-0.95,0) 2(0.95,0)
SC70-6H43
  rect 0.406x0.838 smd: 1(-0.65,-0.925) 2(0,-0.925) 3(0.65,-0.925) 4(0.65,0.925) 5(0,0.925) 6(-0.65,0.925)
SOT23-5L-2
  rect 0.61x1.194 smd: 1(-0.95,-1.15) 2(0,-1.15) 3(0.95,-1.15) 4(0.95,1.15) 5(-0.95,1.15)
TSSOP8
  rect 0.33x1.651 smd: 1(-0.975,-2.92) 2(-0.325,-2.92) 3(0.325,-2.92) 4(0.975,-2.92) 5(0.975,2.92) 6(0.325,2.92) 7(-0.325,2.92) 8(-0.975,2.92)
unnamed#2
  round 3.937 hole 2.667 unplated: (0,0)
YSML276W197H71
  rect 1.803x2.007 smd: 1(-2.54,-2) 2(0,-2) 3(2.54,-2) 4(2.54,2) 5(0,2) 6(-2.54,2)

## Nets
AGND_A: M2.10 M2.SH1 M2.SH2(SHIELD_1)
AGND_B: M1.10 M1.SH1 M1.SH2(SHIELD_1)
AVDD_3P3: C6.1 C7.1 C8.1 C9.1 C16.1 C17.2(N2) C53.1 C54.1 C55.1 C56.1 C63.1 C64.2(N2) E1.1 U1.11 U1.20 U2.11 U2.20 U9.1
DGND: C1.2(N2) C2.2(N2) C3.2(N2) C4.2(N2) C5.2(N2) C6.2(N2) C7.2(N2) C8.2(N2) C9.2(N2) C10.2(N2) C11.2(N2) C12.2(N2) C13.2(N2) C14.2(N2) C15.1 C16.2(N2) C17.1 C18.2(N2) C19.1 C20.2(N2) C21.2(N2) C22.2(N2) C23.2(N2) C24.2(N2) C25.2(N2) C26.1 C27.2(N2) C34.1 C36.2(N2) C37.2(N2) C39.1 C40.2(N2) C41.2(N2) C42.2(N2) C43.2(N2) C44.2(N2) C45.2(N2) C46.2(N2) C47.2(N2) C48.2(N2) C49.2(N2) C50.2(N2) C51.2(N2) C52.2(N2) C53.2(N2) C54.2(N2) C55.2(N2) C56.2(N2) C57.2(N2) C58.2(N2) C59.2(N2) C60.2(N2) C61.2(N2) C62.1 C63.2(N2) C64.1 C65.2(N2) C66.2(N2) C67.1 C68.2(N2) C69.2(N2) C70.2(N2) C73.2(N2) C74.2(N2) C75.2(N2) C76.2(N2) C77.2(N2) C78.2(N2) C79.2(N2) C83.2(N2) D1.2 D2.2 D4.2 D5.2 P2.2 P2.4 P2.6 P2.8(N4) P3.1(N1) P6.2 P6.4 P6.6 P6.8(N4) P8.C1 P8.C4 P8.C5 P8.C8 P8.C9 P8.C12 P8.C13 P8.C16 P8.C17 P8.C20 P8.C21 P8.C24 P8.C25 P8.C28 P8.C29 P8.C32 P8.C33 P8.C36 P8.C38 P8.C40 P8.D2 P8.D3 P8.D6 P8.D7 P8.D10 P8.D13 P8.D16 P8.D19 P8.D22 P8.D25 P8.D28 P8.D37 P8.D39 P8.G1 P8.G4 P8.G5 P8.G8 P8.G11 P8.G14 P8.G17 P8.G20 P8.G23 P8.G26 P8.G29 P8.G32 P8.G35 P8.G38 P8.G40 P8.H2 P8.H3 P8.H6 P8.H9(N9) P8.H12 P8.H15 P8.H18 P8.H21 P8.H24 P8.H27 P8.H30 P8.H33 P8.H36 P8.H39 R3.1 R9.2(N2) R12.2(N2) R15.2(N2) R17.2(N2) R19.2(N2) R21.2(N2) R27.2(N2) R32.2(N2) R34.2(N2) R38.2(N2) R40.2(N2) R44.2(N2) R46.2(N2) R54.1 R69.1 R75.2(N2) R78.2(N2) R81.2(N2) R83.2(N2) R85.2(N2) R87.2(N2) U1.5 U1.PAD2 U2.5 U2.PAD2 U3.4 U3.5 U4.5 U4.PAD U5.3 U6.3 U7.4 U7.7(WC_N) U8.3 U8.4 U8.7(WC_N) U9.4 U9.5 U10.4 U10.5 U11.4 U11.5 U12.4 U12.5 U13.4 U13.5 U14.4 U14.5 U15.1 U15.2 U15.PAD Y1.3 Y2.3 Y3.3
DVDD_3P3: C36.1 C37.1 C77.1 C79.1 C83.1 E1.2(N2) P8.C39 P8.D38 P8.D40 R2.1 R28.2(N2) R43.1 R45.1 R53.2(N2) R68.1 U4.1(VIN) U4.2 U4.4 U10.8(VCCB) U11.8(VCCB) U12.8(VCCB) U13.8(VCCB)
VDD_0P9: C1.1 C2.1 C10.1 C11.1 C14.1 C15.2(N2) C22.1 C23.1 C39.2(N2) C48.1 C49.1 C57.1 C58.1 C61.1 C62.2(N2) C69.1 C70.1 L1.2(N2) R55.2(N2) U1.4 U1.28 U1.36 U2.4 U2.28 U2.36
VDD_ADJ: C4.1 C5.1 C12.1 C13.1 C18.1 C19.2(N2) C20.1 C21.1 C41.1 C43.1 C45.1 C47.1 C51.1 C52.1 C59.1 C60.1 C65.1 C66.1 C67.2(N2) C68.1 C74.1 C75.1 C76.1 L2.2(N2) L3.2(N2) P8.G39 P8.H40 R5.1 R6.1 R8.1 R11.1 R14.1 R16.1 R18.1 R20.1 R31.1 R33.1 R37.1 R39.1 R71.1 R72.1 R74.1 R77.1 R80.1 R82.1 R84.1 R86.1 U1.25 U1.31 U1.40 U2.25 U2.31 U2.40 U3.1 U9.8(VCCB) U10.1 U11.1 U12.1 U13.1 U14.8(VCCB)
AUX_3P3: C24.1 C25.1 C27.1 C73.1 C78.1 P8.D32 R13.1 R26.1 R47.2(N2) R48.1 R49.2(N2) R76.1 U3.8(VCCB) U5.5 U6.5 U7.3 U7.8 U8.8 U14.1 U15.4 Y1.6(VDD) Y2.6(VDD) Y3.1 Y3.6(VDD)
FB: R54.2(N2) R55.1 U4.3
FMC_RESET_A: C42.1 P8.H19 R58.1 R60.2(N2) U3.2
FMC_RESET_B: C46.1 P8.H20 R58.2(N2) R64.2(N2) U3.3
FPGA_LED_0_A: P8.G12 U9.7
FPGA_LED_0_B: P8.D23 U9.6
GA0: P8.C34 U7.1 U8.1
GA1: P8.D35 U7.2 U8.2
GP_CLK/RX_ER_A: P8.D9 R29.1 U2.27
GP_CLK/RX_ER_B: P8.D21 R30.1 U1.27
INT_N/CRS_A: P4.1(N1) P8.G13 R6.2(N2) U2.22
INT_N/CRS_B: P7.1(N1) P8.D24 R72.2(N2) U1.22
LED_0_A: DS4.C R4.2(N2) R42.1 U9.2
LED_0_B: DS2.C R41.1 R70.2(N2) U9.3
LED_AL_A: M2.14 U13.6
LED_AL_A_C2M: P8.D18 U13.3
LED_AL_C: M2.13 R25.2(N2)
LED_AL_C_C2M: P8.D17 U13.2
LED_AR_A: M2.12 U12.6
LED_AR_A_C2M: P8.G16 U12.3
LED_AR_C: M2.11 R24.2(N2)
LED_AR_C_C2M: P8.G15 U12.2
LED_BL_A: M1.14 U11.6
LED_BL_A_C2M: P8.D27 U11.3
LED_BL_C: M1.13 R23.2(N2)
LED_BL_C_C2M: P8.D26 U11.2
LED_BR_A: M1.12 U10.6
LED_BR_A_C2M: P8.G19 U10.3
LED_BR_C: M1.11 R22.2(N2)
LED_BR_C_C2M: P8.G18 U10.2
LINK_ST_A: P8.H10 R35.1 U2.26
LINK_ST_B: P8.G27 R36.1 U1.26
MDC_FMC_A: P8.H17 R56.1 R61.2(N2) U2.23
MDC_FMC_B: P8.H32 R56.2(N2) R65.2(N2) U1.23
MDI_0A_N: D1.3 M2.3 U2.13
MDI_0A_P: D1.1 M2.2 U2.12
MDI_0B_N: D4.3 M1.3 U1.13
MDI_0B_P: D4.1 M1.2 U1.12
MDI_1A_N: D1.6 M2.5 U2.15
MDI_1A_P: D1.4 M2.4 U2.14
MDI_1B_N: D4.6 M1.5 U1.15
MDI_1B_P: D4.4 M1.4 U1.14
MDI_2A_N: D2.3 M2.7 U2.17
MDI_2A_P: D2.1 M2.6 U2.16
MDI_2B_N: D5.3 M1.7 U1.17
MDI_2B_P: D5.1 M1.6 U1.16
MDI_3A_N: D2.6 M2.9 U2.19
MDI_3A_P: D2.4 M2.8 U2.18
MDI_3B_N: D5.6 M1.9 U1.19
MDI_3B_P: D5.4 M1.8 U1.18
MDIO_FMC_A: P8.H16 R5.2(N2) R57.1 R62.2(N2) U2.24
MDIO_FMC_B: P8.H31 R57.2(N2) R66.2(N2) R71.2(N2) U1.24
PG_C2M: P8.D1 U5.1 U6.1
RESET_A: R1.1 U5.4(Y)
RESET_B: R67.1 U6.4(Y)
RX_CTL/RX_DV_A: P8.H14 R11.2(N2) R12.1 U2.35
RX_CTL/RX_DV_B: P8.H29 R77.2(N2) R78.1 U1.35
RXC/RX_CLK_A: P8.G6 R8.2(N2) R9.1 U2.34
RXC/RX_CLK_B: P8.C22 R74.2(N2) R75.1 U1.34
RXD_0A: P8.H7 R20.2(N2) R21.1 U2.33
RXD_0B: P8.H22 R86.2(N2) R87.1 U1.33
RXD_1A: P8.H8 R18.2(N2) R19.1 U2.32
RXD_1B: P8.H23 R84.2(N2) R85.1 U1.32
RXD_2A: P8.G9 R16.2(N2) R17.1 U2.30
RXD_2B: P8.G21 R82.2(N2) R83.1 U1.30
RXD_3A: P8.G10 R14.2(N2) R15.1 U2.29
RXD_3B: P8.G22 R80.2(N2) R81.1 U1.29
SCL: R7.1 R13.2(N2) U7.6 U8.6 U15.10 Y2.2
SCLOUT1: R47.1 U15.9 Y1.2
SDA: R10.1 R76.2(N2) U7.5 U8.5 U15.7 Y2.1
SDAOUT1: R49.1 U15.8 Y1.1
TX_CTL/TX_EN_A: P8.H13 U2.37
TX_CTL/TX_EN_B: P8.H28 U1.37
TXC/TX_CLK_A: P8.H11 U2.38
TXC/TX_CLK_B: P8.G28 U1.38
TXD_0A: P8.D14 U2.39
TXD_0B: P8.H25 U1.39
TXD_1A: P8.D15 U2.1
TXD_1B: P8.H26 U1.1
TXD_2A: P8.C10 U2.2
TXD_2B: P8.G24 U1.2
TXD_3A: P8.C11 U2.3
TXD_3B: P8.G25 U1.3
UNNAMED_2_ADIN1300_I19_CLK25REF: CLK25A.1(N1) U2.6
UNNAMED_2_ADIN1300_I19_LED0: R4.1 U2.21
UNNAMED_2_ADIN1300_I19_RESETN: C3.1 R1.2(N2) R2.2(N2) U2.7
UNNAMED_2_ADIN1300_I19_REXT: R3.2(N2) U2.10
UNNAMED_2_ADLTC4316_I318_ENABLE: R26.2(N2) U15.5
UNNAMED_2_ADLTC4316_I318_XORL: R27.1 R48.2(N2) U15.3(XORL)
UNNAMED_4_CAP_I33_N2: C34.2(N2) M1.1
UNNAMED_4_DIOLED_I25_P: DS2.A(P) R28.1
UNNAMED_4_ICNLSV2T240_I38_B1: R23.1 U11.7
UNNAMED_4_ICNLSV2T240_I41_B1: R22.1 U10.7
UNNAMED_6_RES_I1_N2: R29.2(N2) R31.2(N2) R32.1
UNNAMED_6_RES_I11_N2: R35.2(N2) R37.2(N2) R38.1
UNNAMED_6_RES_I12_N2: R42.2(N2) R45.2(N2) R46.1
UNNAMED_6_RES_I14_N2: R36.2(N2) R39.2(N2) R40.1
UNNAMED_6_RES_I17_N2: R41.2(N2) R43.2(N2) R44.1
UNNAMED_6_RES_I21_N2: R30.2(N2) R33.2(N2) R34.1
UNNAMED_7_CAP_I72_N2: C26.2(N2) M2.1
UNNAMED_7_DIOLED_I63_P: DS4.A(P) R53.1
UNNAMED_7_ICNLSV2T240_I75_B1: R24.1 U12.7
UNNAMED_7_ICNLSV2T240_I76_B1: R25.1 U13.7
UNNAMED_9_74109V2_I253_B: U3.6 U6.2
UNNAMED_9_74109V2_I254_B: U3.7 U5.2
UNNAMED_9_ADLT3502_I252_BOOST: C38.1 U4.7
UNNAMED_9_ADLT3502_I252_DA: D3.A(P) U4.6
UNNAMED_9_CAP_I244_N2: C38.2(N2) D3.C L1.1 U4.8
UNNAMED_10_CAP_I161_N1: C40.1 L2.1 R59.2(N2)
UNNAMED_10_CAP_I224_N1: C44.1 L3.1 R63.2(N2)
UNNAMED_10_CN8PODDEVENV2_I25_N1: P6.1 R59.1
UNNAMED_10_CN8PODDEVENV2_I25_N2: P6.3 R61.1
UNNAMED_10_CN8PODDEVENV2_I25_N3: P6.5 R62.1
UNNAMED_10_CN8PODDEVENV2_I25_N4: P6.7 R60.1
UNNAMED_10_CN8PODDEVENV2_I223_1: P2.3 R65.1
UNNAMED_10_CN8PODDEVENV2_I223_2: P2.5 R66.1
UNNAMED_10_CN8PODDEVENV2_I223_3: P2.7 R64.1
UNNAMED_10_CN8PODDEVENV2_I223_N: P2.1 R63.1
UNNAMED_12_ADIN1300_I137_CLK25R: CLK25B.1(N1) U1.6
UNNAMED_12_ADIN1300_I137_LED0: R70.1 U1.21
UNNAMED_12_ADIN1300_I137_RESETN: C50.1 R67.2(N2) R68.2(N2) U1.7
UNNAMED_12_ADIN1300_I137_REXT: R69.2(N2) U1.10
UNNAMED_13_CN160PCDGH_I191_N30: P8.D30 P8.D31
UNNAMED_13_CN160PCDGH_I193_N30: P8.C30 R7.2(N2)
UNNAMED_13_CN160PCDGH_I193_N31: P8.C31 R10.2(N2)
UNNAMED_13_CN160PCDGH_I222_N4: P8.H4 Y3.4
UNNAMED_13_CN160PCDGH_I222_N5: P8.H5 Y3.5
XTAL_I_A: U2.9 Y1.4
XTAL_I_B: U1.9 Y2.4
XTAL_REF_A: U14.2 Y1.5
XTAL_REF_A_FMC: P8.D8 U14.7
XTAL_REF_B: U14.3 Y2.5
XTAL_REF_B_FMC: P8.D20 U14.6

Pads without a net: D1 5; D2 5; D4 5; D5 5; P8 C2 C3 C6 C7 C14 C15 C18 C19 C23 C26 C27 C35 C37 D4 D5 D11 D12 D29 D33 D34 D36 G2 G3 G7 G30 G31 G33 G34 G36 G37 H1 H34 H35 H37 H38; U1 8 PAD1 PAD3; U2 8 PAD1 PAD3; U15 6; Y3 2

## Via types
v1: diameter 0.508, hole 0.254, TOP to BOTTOM, 582 vias

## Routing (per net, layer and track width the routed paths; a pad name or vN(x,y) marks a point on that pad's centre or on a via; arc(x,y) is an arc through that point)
AGND_A: length 62.9
  TOP w0.508: 15.62,49.57 M2.SH1 14.13,48.08 ; 17.43,48.64 M2.10 16.32,47.54
  L2_GND w0.508: 16.43,47.54 M2.10 17.43,48.54 ; 14.13,48.18 M2.SH1 15.56,49.57 15.81,49.32 ; 15.28,32.92 M2.SH2 12.98,32.92
  L3_SIG w0.508: 15.62,49.57 M2.SH1 14.13,48.08 ; 16.32,47.54 M2.10 17.43,48.64 ; 15.28,32.92 M2.SH2 12.98,32.92
  L4_GND w0.508: 16.32,47.54 M2.10 17.43,48.64 ; 15.28,32.92 M2.SH2 12.98,32.92 ; 14.13,48.08 M2.SH1 15.62,49.57
  L5_PWR w0.508: 14.13,48.08 M2.SH1 15.62,49.57 ; 16.32,47.54 M2.10 17.43,48.64 ; 12.98,32.92 M2.SH2 15.28,32.92
  L6_SIG w0.508: 16.32,47.54 M2.10 17.43,48.64 ; 14.13,48.08 M2.SH1 15.62,49.57 ; 15.28,32.92 M2.SH2 12.98,32.92
  L7_GND w0.508: 14.13,48.08 M2.SH1 15.62,49.57 ; 17.43,48.54 M2.10 ; 15.28,32.92 M2.SH2 12.98,32.92
  BOTTOM w0.508: 14.13,48.18 M2.SH1 15.56,49.57 15.81,49.32 ; 17.43,48.54 M2.10 16.43,47.54 ; 15.21,33 M2.SH2 13.05,33
AGND_B: length 74.5
  TOP w0.508: 17.43,24.26 M1.10 16.32,23.15
  L2_GND w0.508: M1.SH1 15.28,24.03 ; M1.SH1 15.28,26.34 ; M1.SH1 12.98,26.34 ; 16.32,23.15 M1.10 17.43,24.26 ; 12.98,8.54 M1.SH2 15.28,8.54
  L3_SIG w0.508: 17.43,24.26 M1.10 16.32,23.15 ; 12.98,26.34 M1.SH1 ; M1.SH1 15.28,24.03 ; M1.SH1 15.28,26.34 ; 15.28,8.54 M1.SH2 12.98,8.54
  L4_GND w0.508: 15.28,8.54 M1.SH2 12.98,8.54 ; 17.43,24.26 M1.10 16.32,23.15 ; M1.SH1 15.28,26.34 ; M1.SH1 12.98,26.34 ; M1.SH1 15.28,24.03
  L5_PWR w0.508: 15.28,26.34 M1.SH1 ; M1.SH1 15.28,24.03 ; M1.SH1 12.98,26.34 ; 17.43,24.26 M1.10 16.32,23.15 ; 12.98,8.54 M1.SH2 15.28,8.54
  L6_SIG w0.508: 16.32,23.15 M1.10 17.43,24.26 ; M1.SH1 15.28,26.34 ; M1.SH1 15.28,24.03 ; M1.SH1 12.98,26.34 ; 12.98,8.54 M1.SH2 15.28,8.54
  L7_GND w0.508: 12.98,26.34 M1.SH1 ; M1.SH1 15.28,24.03 ; M1.SH1 15.28,26.34 ; 16.43,23.15 M1.10 17.43,24.16 ; 15.28,8.54 M1.SH2 12.98,8.54
  BOTTOM w0.508: M1.SH1 15.28,24.03 ; M1.SH1 12.98,26.34 ; M1.SH1 15.28,26.34 ; 17.43,24.26 M1.10 16.32,23.15 ; 12.98,8.54 M1.SH2 15.28,8.54
AVDD_3P3: length 24.9
  TOP w0.305: U9.1 54.92,30.4 v1(54.8,30.52)
  TOP w0.508: C55.1 42.82,17.94 C56.1 42.13,17.96 v1(41.91,18.19) ; v1(41.88,42.75) 42.11,42.52 C9.1 43.76,42.52 C8.1
  BOTTOM w0.279: U1.11 42.82,13.27 42.15,12.6
  BOTTOM w0.305: v1(41.88,42.75) 42.3,42.33 U2.20 ; U1.20 42.32,17.77 v1(41.91,18.19) ; 42.68,37.69 42.82,37.83 U2.11
  BOTTOM w0.508: C64.2 v1(37.27,22.52) ; v1(38.67,47.28) 37.73,47.28 C17.2 ; C63.1 39.62,22.93 v1(39.21,22.52) ; 42.15,12.58 C54.1 ; 42.15,12.58 42.15,12.6 ; 42.15,12.58 C53.1 v1(42.92,11.58) ; C16.1 v1(39.59,47.19) ; 42.68,37.69 42.4,37.42 C7.1 41.87,37.39 C6.1 ; 41.72,8.22 E1.1 ; E1.1 42.52,7.44 ; E1.1 40.92,7.44
  BOTTOM w0.559: C6.1 v1(42.62,36.4)
  vias: v1(41.21,8.42) v1(42.22,8.42)
DGND: length 627.7
  TOP w0.203: v1(30.54,27.6) 30.54,27.47 30.34,27.27 U11.4 ; v1(30.54,33.31) 30.54,33.19 30.34,32.98 U12.4 U12.5 28.2,32.98 28,33.19 v1(28,33.53) ; 30.54,9.06 v1(30.65,9.16) ; 44.51,25.45 44.52,25.45
  TOP w0.229: U14.5 57.56,45.54 v1(57.72,45.38) ; U9.5 57.58,29.16 ; U9.5 56.91,28.74 ; U9.5 U9.4 55.45,29.16 55.18,28.88 55.18,28.48 v1(55.19,28.48) ; v1(28,9.06) 28.2,8.85 U10.5 U10.4 30.34,8.85 30.54,9.06 ; v1(30.54,51.6) 30.34,51.4 U13.4 U13.5 28.2,51.4 ; v1(55.99,44.97) U14.4 55.59,45.54 55.3,45.25 ; U11.4 U11.5 27.82,27.27 v1(27.62,27.47)
  TOP w0.305: v1(72.83,20.57) 72.6,20.34 U8.4 ; U8.4 72.6,17.87 ; U8.4 73.07,19 ; U7.7 v1(67.23,26.33) ; 40.32,21.13 40.42,21.13 ; 71.95,17.82 U8.3 71.95,20.35 v1(71.71,20.59) ; 68.93,19 U7.4 68.53,17.89 v1(68.83,17.59) ; 56.84,51.73 56.84,51.61 56.83,51.6 ; 58.61,33.81 58.73,33.81 58.73,33.82 ; U8.7 71.3,23.76 v1(71.56,23.49)
  TOP w0.508: 47.48,24.93 C61.2 ; C61.2 48.51,25.81 ; C61.2 49.62,24.93 49.74,25.05 C62.1 51.05,26.15 ; C15.1 51.06,50.12 v1(52.26,48.92) ; C15.1 51.02,51.22 ; C15.1 50.53,49.62 C14.2 ; 58.23,22.35 R78.2 v1(57.46,23.03) ; C48.2 46.22,14.38 ; C48.2 47.24,13.48 ; C48.2 46.2,13.46 C50.2 45.21,14.38 ; C57.2 48.26,15.29 C58.2 47.62,15.27 ; C57.2 47.62,16.28 ; C57.2 48.26,17.04 C69.2 C66.2 44.83,16.61 ; 42.9,50.62 C65.2 ; C65.2 41.87,49.75 ; C65.2 43.92,49.75 ; 56.84,51.73 R21.2 v1(56.06,52.24) ; 58.86,10.57 C74.2 ; C74.2 60.13,10.57 ; C74.2 59.5,11.17 ; 58.61,33.81 R87.2 58.1,34.39 v1(57.84,34.65) ; 33.73,56.49 P2.4 ; P2.4 34.96,57.72 ; P2.4 36.19,56.49 ; C8.2 43.78,44.25 v1(43.62,44.41) ; C68.2 45.84,16.74 ; P6.6 49.56,57.72 ; P6.6 50.8,56.49 ; P6.6 48.33,56.49 ; C19.1 47.28,25.05 ; C19.1 44.68,25.05 ; C19.1 45.97,26.15 ; C83.2 66.1,8.72 ; C83.2 65.45,9.32 65.28,9.15 v1(65.28,9.06) ; C83.2 66.74,9.32 ; C22.2 47.84,42 C23.2 ; C22.2 45.82,42 ; C22.2 46.83,41.24 ; 34.35,27.34 35.14,27.34 Y2.3 ; C67.1 44.38,49.99 ; C67.1 45.69,51.09 ; C67.1 47,49.99 ; 42.79,18.94 42.79,19.66 ; 42.79,18.94 v1(41.91,18.94) ; 42.79,18.94 C56.2 43.79,18.92 C55.2 43.81,19.84 ; C75.2 v1(63.18,7.79) ; C78.2 64.45,16.68 ; C78.2 63.43,17.45 ; C78.2 65.33,17.45 ; 47.24,13.48 C49.2 ; 47.24,13.48 47.24,14.38 ; v1(47.34,39.07) 47.21,38.94 C2.2 47.19,38.04 C1.2 46.2,38.94 v1(46.32,39.07) ; P2.2 32.42,57.72 ; P2.2 31.19,56.49 ; P2.2 33.65,56.49 ; 42.46,25.45 C18.2 44.51,25.45 ; P6.8 53.34,56.49 ; P6.8 52.1,57.72 ; P6.8 50.87,56.49 ; 67.24,31.24 R75.2 67.86,31.92 ; C14.2 47.58,49.62 ; C14.2 48.61,50.49 ; 47.62,14.25 C52.2 48.26,13.26 C51.2 ; P2.6 37.5,57.72 ; P2.6 38.73,56.49 ; P2.6 36.27,56.49 ; 64.05,48.55 R15.2 63.43,49.23 ; C4.2 50.1,43.7 v1(50.1,44.25) ; 64.17,52.24 R9.2 63.55,51.56 ; C76.2 v1(62.16,7.79) ; 45.82,42 C12.2 44.8,41.26 ; 45.82,42 C21.2 ; 45.82,42 45.82,41.21 ; 56.84,49.02 R19.2 56.21,49.7 ; Y2.3 35.21,28.74 34.48,28.74 ; Y2.3 v1(35.87,26.58) ; v1(61.61,35.09) 61.53,35.09 61.52,35.08 R83.2 ; P2.8 40.04,57.72 ; P2.8 41.27,56.49 ; P2.8 38.81,56.49 ; 46.8,31.05 P3.1 45.59,29.84 ; 47.59,40.84 C10.2 48.24,39.85 C11.2 47.59,39.83 ; v1(45.31,39.07) 45.18,38.94 C3.2 ; v1(48.89,19.56) C59.2 49.89,18.81 C60.2 49.91,19.37 50.1,19.56 v1(50.1,19.56) ; C70.2 46.86,16.74 ; 62.54,10.46 C79.2 63.81,10.46 ; 40.95,20.53 C25.2 ; C25.2 41.59,21.13 ; C25.2 40.42,21.13 ; 44.48,57.72 P6.2 45.72,56.49 ; P6.4 47.02,57.72 ; P6.4 48.26,56.49 ; P6.4 45.79,56.49 ; R85.2 60.63,30.02 ; C13.2 48.24,37.82 C20.2 47.59,38.81 ; v1(56.96,41.25) R12.2 56.34,42.08 ; v1(41.87,43.5) 41.9,43.48 C9.2 ; 43.49,31.91 C24.2 42.31,31.91 ; 64.32,33.19 R81.2 63.43,32.51 ; C5.2 v1(48.86,44.25) ; Y1.3 35.87,33.75 ; Y1.3 34.67,35.06 ; Y1.3 35.87,36.37 ; R17.2 63.05,49.7 ; 61.15,15.91 C77.2 62.54,17.18
  L2_GND w0.508: 38.81,56.49 P2.8 ; P2.8 41.27,56.49 ; P2.8 40.04,57.72 ; 52.1,55.26 P6.8 ; P6.8 53.34,56.49 ; P6.8 50.87,56.49 ; P6.8 52.1,57.72 ; P2.4 36.19,56.49 ; P2.4 34.96,57.72 ; P2.4 34.96,55.26 ; P2.4 33.73,56.49 ; P3.1 48,29.84 ; P3.1 46.8,28.64 ; P3.1 45.59,29.84 ; P3.1 46.8,31.05 ; 47.02,55.26 P6.4 ; P6.4 47.02,57.72 ; P6.4 48.26,56.49 ; P6.4 45.79,56.49 ; P6.6 50.8,56.49 ; P6.6 49.56,57.72 ; P6.6 49.56,55.26 ; P6.6 48.33,56.49 ; 31.19,56.49 P2.2 ; P2.2 33.65,56.49 ; P2.2 32.42,55.26 ; P2.2 32.42,57.72 ; P2.6 38.73,56.49 ; P2.6 37.5,55.26 ; P2.6 36.27,56.49 ; P2.6 37.5,57.72 ; 44.48,55.26 P6.2 ; P6.2 43.25,56.49 ; P6.2 44.48,57.72 ; P6.2 45.72,56.49
  L3_SIG w0.508: 37.5,55.26 P2.6 ; P2.6 38.73,56.49 ; P2.6 37.5,57.72 ; P2.6 36.27,56.49 ; P2.4 36.19,56.49 ; P2.4 34.96,57.72 ; P2.4 34.96,55.26 ; P2.4 33.73,56.49 ; P6.6 50.8,56.49 ; P6.6 48.33,56.49 ; P6.6 49.56,55.26 ; P6.6 49.56,57.72 ; 38.81,56.49 P2.8 ; P2.8 41.27,56.49 ; P2.8 40.04,57.72 ; P6.2 44.48,57.72 ; P6.2 43.25,56.49 ; P6.2 45.72,56.49 ; P6.2 44.48,55.26 ; P6.4 48.26,56.49 ; P6.4 45.79,56.49 ; P6.4 47.02,55.26 ; P6.4 47.02,57.72 ; P3.1 46.8,31.05 ; P3.1 48,29.84 ; P3.1 45.59,29.84 ; P2.2 33.65,56.49 ; P2.2 31.19,56.49 ; P2.2 32.42,55.26 ; P2.2 32.42,57.72 ; 50.87,56.49 P6.8 ; P6.8 52.1,55.26 ; P6.8 53.34,56.49 ; P6.8 52.1,57.72
  L4_GND w0.508: P6.8 53.34,56.49 ; P6.8 50.87,56.49 ; P6.8 52.1,55.26 ; P6.8 52.1,57.72 ; P2.6 37.5,57.72 ; P2.6 37.5,55.26 ; P2.6 38.73,56.49 ; P2.6 36.27,56.49 ; 34.96,55.26 P2.4 ; P2.4 36.19,56.49 ; P2.4 33.73,56.49 ; P2.4 34.96,57.72 ; 48.33,56.49 P6.6 ; P6.6 50.8,56.49 ; P6.6 49.56,57.72 ; P6.6 49.56,55.26 ; P6.4 48.26,56.49 ; P6.4 47.02,55.26 ; P6.4 45.79,56.49 ; P6.4 47.02,57.72 ; 38.81,56.49 P2.8 ; P2.8 40.04,57.72 ; P2.8 41.27,56.49 ; 32.42,55.26 P2.2 ; P2.2 32.42,57.72 ; P2.2 33.65,56.49 ; P2.2 31.19,56.49 ; P3.1 46.8,31.05 ; P3.1 48,29.84 ; P3.1 46.8,28.64 ; P3.1 45.59,29.84 ; 44.48,55.26 P6.2 ; P6.2 44.48,57.72 ; P6.2 43.25,56.49 ; P6.2 45.72,56.49
  L6_SIG w0.508: 46.8,28.64 P3.1 48,29.84
  L6_SIG w1.27: 31.29,56.49 P2.2 P2.4 P2.6 P2.8 41.17,56.49 ; 43.35,56.49 P6.2 P6.4 P6.6 P6.8 53.24,56.49
  L7_GND w0.508: 48.33,56.49 P6.6 ; P6.6 50.8,56.49 ; P6.6 49.56,57.72 ; P6.6 49.56,55.26 ; P6.4 47.02,57.72 ; P6.4 45.79,56.49 ; P6.4 47.02,55.26 ; P6.4 48.26,56.49 ; 37.5,55.26 P2.6 ; P2.6 36.27,56.49 ; P2.6 38.73,56.49 ; P2.6 37.5,57.72 ; P6.2 45.72,56.49 ; P6.2 43.25,56.49 ; P6.2 44.48,57.72 ; P6.2 44.48,55.26 ; P2.4 34.96,57.72 ; P2.4 36.19,56.49 ; P2.4 33.73,56.49 ; P2.4 34.96,55.26 ; 45.59,29.84 P3.1 ; P3.1 46.8,31.05 ; P3.1 46.8,28.64 ; P3.1 48,29.84 ; P2.2 32.42,57.72 ; P2.2 32.42,55.26 ; P2.2 33.65,56.49 ; P2.2 31.19,56.49 ; P2.8 41.27,56.49 ; P2.8 38.81,56.49 ; P2.8 40.04,57.72 ; P6.8 53.34,56.49 ; P6.8 52.1,57.72 ; P6.8 50.87,56.49 ; P6.8 52.1,55.26
  BOTTOM w0.203: 40.65,25.69 40.62,25.69 ; 65.18,28.2 65.12,28.27 ; 40.61,50.13 40.45,50.13
  BOTTOM w0.229: U3.5 53.33,30.76 v1(53.14,30.57) ; U3.5 53.03,31.26 52.85,31.08 52.85,30.72 ; U3.5 U3.4 54.87,31.26 55.03,31.09
  BOTTOM w0.254: U15.PAD 24.2,29 ; 24.2,29 24.2,28.76 23.94,28.5 U15.1 ; 24.2,29 U15.2 ; U15.1 22.49,28.5 ; U15.1 23.2,28.07 ; 52.85,30.72 53,30.57 v1(53.14,30.57)
  BOTTOM w0.279: U1.5 46.6,13.64 46.35,13.89 v1(46.35,14.5) ; U2.5 46.57,38.21 46.32,38.46 v1(46.32,39.07)
  BOTTOM w0.305: P8.G8 60.29,50.87 ; P8.G8 61.37,49.79 ; P8.G8 61.37,50.87 ; 66.45,44.52 P8.C13 ; P8.C13 v1(65.28,44.62) ; P8.C13 v1(66.55,43.35) ; P8.C13 v1(65.28,43.35) P8.D13 ; v1(65.28,44.62) P8.C12 ; v1(65.28,44.62) P8.D13 ; P8.C12 v1(66.55,45.88) ; P8.C12 v1(66.55,44.62) ; 61.46,9.69 P8.G40 ; P8.G40 60.83,9.07 ; P8.G40 60.28,10.24 v1(60.28,10.33) ; 64.1,33.09 P8.D22 ; P8.D22 v1(65.28,33.19) P8.C21 ; P8.D22 v1(64.01,31.92) ; P8.C4 v1(66.55,54.78) P8.C5 ; P8.C4 66.45,55.95 ; P8.C4 v1(65.28,54.78) P8.C5 ; P8.C4 65.05,56.27 P8.D3 ; P8.H39 P8.G38 ; P8.H39 60.1,10.42 ; P8.H39 v1(58.93,11.6) ; P8.H39 59.02,10.42 ; P8.G38 61.37,11.69 ; P8.G38 61.37,12.77 ; P8.G38 60.29,12.77 ; P8.C8 v1(65.28,49.7) P8.C9 ; P8.C8 v1(66.55,50.96) ; P8.C8 P8.D7 ; P8.C8 v1(66.55,49.7) ; 59.02,29.47 P8.H24 60.1,29.47 ; v1(65.24,25.53) P8.D28 ; P8.D28 64.1,25.47 ; P8.D28 64.1,24.39 ; P8.D28 v1(65.28,24.3) ; 66.45,24.2 P8.C29 ; P8.C29 66.45,23.12 ; P8.C29 v1(65.28,24.3) ; P8.C29 v1(65.28,23.03) ; 66.45,30.55 P8.C24 ; P8.C24 66.45,29.47 ; P8.C24 v1(65.28,29.38) P8.D25 ; P8.C24 v1(65.28,30.65) ; P8.C9 v1(65.28,48.43) P8.D10 ; P8.C9 66.45,49.6 ; P8.C9 v1(66.55,48.43) ; v1(61.47,56.04) P8.G4 ; P8.G4 60.29,54.87 ; P8.G4 v1(60.2,56.05) P8.H3 ; P8.G4 61.37,54.87 ; v1(64.01,10.41) 64.1,10.41 P8.D39 v1(65.28,11.6) P8.C38 ; P8.C5 v1(65.28,53.51) P8.D6 ; P8.C5 v1(66.55,53.51) ; 61.37,16.58 P8.G35 ; P8.G35 60.29,16.58 ; P8.G35 v1(60.23,15.44) P8.H36 ; P8.G35 61.37,15.5 ; 60.29,58.68 P8.G1 ; P8.G1 60.29,59.76 ; P8.G1 v1(61.47,58.59) ; P8.C20 66.52,34.49 v1(66.58,34.49) P8.C21 ; P8.C20 P8.D19 ; P8.C20 v1(66.58,35.76) ; P8.C16 v1(66.55,39.54) P8.C17 ; P8.C16 v1(66.55,40.8) ; P8.C16 v1(65.28,39.54) ; P8.C16 65.37,40.71 ; 60.1,25.66 P8.H27 P8.G26 ; 64.1,48.33 P8.D10 ; P8.D10 v1(64.01,47.16) ; P8.H36 60.1,14.23 ; P8.H36 59.02,15.31 ; P8.G26 61.37,28.01 ; P8.G26 61.37,26.93 ; v1(60.2,48.43) P8.H9 59.02,48.52 ; 65.37,59.76 P8.C1 ; P8.C1 66.45,59.76 ; P8.C1 66.45,58.68 ; P8.C1 v1(65.28,58.59) P8.D2 ; P8.D6 v1(65.28,52.24) P8.D7 ; P8.D6 64.1,53.41 ; P8.D6 64.1,52.33 ; 60.2,30.65 P8.G23 ; P8.G23 v1(60.2,31.92) ; P8.G23 61.37,31.82 ; P8.C17 v1(65.28,39.54) ; P8.C17 66.45,38.36 ; v1(65.28,39.54) P8.D16 ; v1(64.04,14.11) P8.D37 ; P8.D37 v1(65.28,14.14) P8.C36 ; P8.D37 P8.C38 ; P8.D37 64.1,12.96 ; 66.45,9.15 P8.C40 ; P8.C40 66.45,10.23 ; P8.C40 v1(65.28,9.06) ; P8.D19 65.18,36.9 ; P8.D19 64.1,36.9 ; 60.1,57.41 P8.H2 ; P8.H2 59.02,58.49 ; P8.H2 60.1,58.49 ; P8.H2 59.02,57.41 ; 59.02,37.09 P8.H18 ; P8.H18 P8.G17 61.37,38.36 ; P8.H18 59.02,38.17 ; P8.C36 66.45,14.23 ; P8.C36 v1(65.28,15.41) ; P8.C36 66.45,15.31 ; P8.D7 64.1,52.14 ; P8.D2 v1(65.28,57.32) ; P8.D2 v1(64.01,57.32) P8.D3 ; v1(61.47,53.51) P8.G5 ; P8.G5 P8.H6 ; P8.G5 v1(61.47,54.77) ; P8.G5 60.29,54.68 ; 66.45,25.47 P8.C28 ; P8.C28 v1(65.28,24.3) ; P8.C28 66.45,24.39 ; P8.C28 65.37,25.47 ; P8.G14 P8.H15 ; P8.G14 61.37,42.17 ; P8.G14 60.29,43.25 ; P8.H15 60.1,40.9 ; P8.H15 59.02,40.9 ; P8.C25 65.37,29.28 ; P8.C25 65.37,28.2 ; P8.C25 66.45,28.2 ; P8.C25 66.45,29.28 ; 59.02,57.22 P8.H3 ; P8.H3 v1(60.2,57.31) ; 60.29,24.2 P8.G29 61.37,23.12 ; 66.45,12.77 P8.C38 ; P8.C38 66.45,11.69 ; P8.H6 60.1,52.33 ; P8.H6 59.02,53.41 ; P8.C33 v1(65.28,19.22) P8.C32 ; P8.C33 66.45,19.12 ; P8.C33 66.45,18.04 ; P8.C33 65.37,18.04 ; P8.D3 64.1,56.14 ; P8.D3 65.18,57.22 ; P8.H33 60.1,18.04 ; P8.H33 59.02,18.04 ; P8.H33 59.02,19.12 ; P8.H30 60.1,21.85 ; P8.H30 59.02,21.85 ; P8.H30 59.02,22.93 ; P8.D13 64.1,44.52 ; P8.D13 v1(64.01,43.35) ; P8.G11 P8.H12 60.1,44.71 ; P8.G11 61.37,45.98 ; P8.G11 v1(61.47,47.15) ; 59.02,34.36 P8.H21 59.02,33.28 ; v1(64.01,28.11) P8.D25 ; P8.D25 65.12,28.27 ; v1(65.24,40.77) P8.D16 ; P8.D16 v1(64.01,39.54) ; 66.45,33.28 P8.C21 ; 61.37,20.39 P8.G32 61.37,19.31 ; P8.C32 66.45,19.31 ; P8.C32 66.45,20.39
  BOTTOM w0.406: D5.2 v1(32.44,19.15) ; D4.2 v1(32.44,11.53) ; D1.2 v1(32.44,36.3) ; D2.2 v1(32.44,43.92)
  BOTTOM w0.508: P6.6 49.56,57.72 ; P6.6 P6.4 ; P6.6 49.56,55.26 ; 44.48,55.26 P6.2 ; P6.2 44.48,57.72 ; P6.2 43.25,56.49 ; P6.2 45.72,56.49 ; P2.4 34.96,57.72 ; P2.4 33.73,56.49 ; P2.4 34.96,55.26 ; C63.2 v1(39.62,26.7) ; C63.2 38.67,25.69 ; C63.2 40.62,25.69 ; 51.62,53.54 Y3.3 52.35,54.34 ; C34.1 23.83,10.71 v1(23.83,10.71) ; C34.1 v1(23.05,9.95) ; C34.1 22.25,10.71 v1(22.25,10.71) ; U6.3 52.17,29.13 52.18,29.12 ; U6.3 50.48,29.13 ; U6.3 v1(51.38,28.37) ; P6.4 47.02,57.67 ; P6.4 47.02,55.03 ; P6.4 45.77,56.49 ; C7.2 40.28,37.42 v1(40.16,37.29) ; v1(40.38,12.6) C54.2 ; U5.3 v1(51.38,31.92) ; P3.1 46.8,28.36 ; P3.1 48.15,29.84 ; P3.1 45.65,29.84 ; 52.1,55.26 P6.8 ; P6.8 53.34,56.49 ; P6.8 52.1,57.72 ; 47.61,64.78 C43.2 ; C43.2 C41.2 ; C43.2 v1(47.05,65.52) ; C41.2 v1(46.03,65.57) ; C41.2 45.43,64.78 ; C17.1 35.87,50.62 ; C17.1 37.18,51.73 ; C17.1 37.68,50.13 C16.2 ; 52.51,48.94 C73.2 53.15,48.34 ; C45.2 v1(33.59,65.57) ; C45.2 32.98,64.78 ; C45.2 C47.2 ; C64.1 34.48,23.75 ; C64.1 34.48,26.37 ; C64.1 35.58,25.06 ; 32.42,55.26 P2.2 ; P2.2 32.42,57.72 ; P2.2 31.19,56.49 ; 39.51,64.74 C46.2 ; C46.2 v1(40.06,65.51) ; C46.2 40.62,64.74 ; R69.1 v1(41.9,10.44) ; R32.2 50.99,50.8 ; C53.2 v1(40.38,11.58) ; 51.82,24.88 R34.2 51.11,25.78 ; 51.57,64.74 C42.2 ; C42.2 v1(52.13,65.53) ; C42.2 52.69,64.74 ; 40.87,35.76 C6.2 40.27,36.4 ; 40.45,50.13 C16.2 ; C16.2 39.59,51.26 ; P8.G20 v1(61.61,35.09) ; C26.1 v1(24.06,35.1) ; C26.1 22.96,34.5 ; C26.1 v1(21.78,35.1) ; C47.2 35.34,64.78 ; C47.2 v1(34.6,65.57) ; R27.2 22.45,27.1 ; R27.2 21.1,27.1 ; R27.2 21.78,26.48 ; v1(61.43,9.06) 61.43,9.1 ; 41.27,56.49 P2.8 40.04,57.72 ; R46.2 42.48,50.8 ; C44.2 v1(32.42,62.52) ; R44.2 42.48,25.78 ; R54.1 5.81,51.98 ; R54.1 5.81,54.36 ; R54.1 4.99,53.24 ; 42.99,34.84 R3.1 43.75,34.22 ; 48.91,24.88 R40.2 48.07,25.65 ; v1(44.49,62.52) C40.2 ; v1(20.9,31.03) C27.2 ; R38.2 47.94,50.67
  BOTTOM w1.016: 24.7,31 U15.PAD 24.7,28
  vias: v1(4,54.01) v1(4,53.21) v1(4,52.45) v1(4.76,54.01) v1(4.76,53.21) v1(4.76,52.45) v1(8.95,56.64) v1(8.95,55.88) v1(8.95,55.12) v1(9.71,56.64) v1(9.71,55.88) v1(10.95,55.91) v1(12.23,55.37) v1(12.25,56.13) v1(13.14,56.13) v1(16.06,18.45) v1(16.06,15.91) v1(16.06,13.37) v1(16.19,20.11) v1(16.32,44.24) v1(16.32,43.22) v1(16.32,41.7) v1(16.32,40.68) v1(16.32,39.16) v1(16.32,38.14) v1(16.32,36.74) v1(16.44,17.18) v1(16.44,14.64) v1(16.44,12.1) v1(17.08,43.73) v1(17.08,41.19) v1(17.08,38.65) v1(17.08,19.34) v1(17.33,36.11) v1(17.71,16.8) v1(17.71,14.26) v1(17.71,11.72) v1(18.09,22.14) v1(18.47,36.62) v1(18.6,35.6) v1(18.73,12.1) v1(18.73,10.96) v1(19.11,22.9) v1(19.24,48.93) v1(19.24,47.41) v1(19.24,34.71) v1(20,10.45) v1(20.38,23.15) v1(20.51,34.71) v1(20.76,47.41) v1(21.4,22.14) v1(21.52,46.27) v1(21.78,34.33) v1(21.78,33.57) v1(22.29,10) v1(22.28,9.29) v1(22.79,21.88) v1(22.92,46.27) v1(22.92,34.33) v1(22.92,33.57) v1(23.05,9.23) v1(23.81,9.95) v1(23.81,9.18) v1(23.94,11.72) v1(24.06,34.33) v1(24.06,33.62) v1(24.14,30.27) v1(24.14,29.5) v1(24.14,28.74) v1(24.19,21.88) v1(24.32,46.27) v1(24.44,36.23) v1(25.08,11.72) v1(25.26,30.27) v1(25.26,29.5) v1(25.26,28.74) v1(25.59,46.78) v1(25.59,35.73) v1(25.59,21.88) v1(26.35,11.6) v1(26.48,34.84) v1(26.6,47.92) v1(26.73,22.14) v1(27.24,10.71) v1(27.62,34.58) v1(27.62,22.9) v1(27.94,51.6) v1(27.87,48.68) v1(28.25,9.82) v1(28.51,23.66) v1(28.89,34.58) v1(29.27,48.68) v1(29.52,9.82) v1(29.74,23.8) v1(30.03,34.58) v1(30.67,48.68) v1(30.89,23.8) v1(31.17,34.58) v1(31.43,9.69) v1(32.06,48.68) v1(32.06,23.79) v1(32.32,34.58) v1(32.7,9.69) v1(33.21,23.79) v1(33.59,48.43) v1(33.59,34.96) v1(33.84,29.5) v1(33.84,28.23) v1(33.84,10.33) v1(34.22,35.98) v1(34.22,11.72) v1(34.35,51.35) v1(34.48,47.41) v1(34.6,26.58) v1(35.24,36.52) v1(35.24,11.72) v1(35.37,22.14) v1(35.62,51.35) v1(35.62,50.08) v1(35.72,47.28) v1(36.38,11.72) v1(36.76,46.27) v1(37.27,20.36) v1(37.52,11.72) v1(37.78,45.25) v1(38.03,36.62) v1(38.16,19.47) v1(38.79,44.24) v1(38.79,12.1) v1(39.05,51.35) v1(39.05,18.58) v1(39.18,37.38) v1(39.68,36.74) v1(39.68,12.87) v1(39.81,43.22) v1(40.19,51.35) v1(40.19,18.33) v1(41.08,42.71) v1(42.22,25.82) v1(42.22,20.49) v1(42.35,33.69) v1(42.64,51.56) v1(42.73,26.47) v1(43.4,51.56) v1(43.56,20.09) v1(43.75,34.07) v1(45.08,26.32) v1(45.27,51.56) v1(45.31,41.1) v1(45.31,40.08) v1(45.33,16.54) v1(45.33,15.52) v1(45.33,14.5) v1(45.97,26.32) v1(46.11,51.56) v1(46.32,41.1) v1(46.32,40.08) v1(46.35,16.54) v1(46.35,15.52) v1(47.34,41.1) v1(47.34,40.08) v1(47.37,16.54) v1(47.37,15.52) v1(47.37,14.5) v1(47.94,26.07) v1(48.1,51.56) v1(48.99,51.54) v1(48.95,26.07) v1(50.86,26.3) v1(51.4,51.56) v1(51.62,26.3) v1(51.88,54.78) v1(52.89,54.78) v1(54.03,48.68) v1(56.57,28.11) v1(56.83,48.17) v1(58.8,17.95) v1(58.93,58.67) v1(58.93,57.4) v1(58.93,53.51) v1(58.93,38.27) v1(58.99,56.05) v1(58.99,54.78) v1(58.96,48.46) v1(58.99,33.19) v1(60.19,58.59) v1(60.19,53.51) v1(60.2,50.97) v1(60.19,47.16) v1(60.2,44.62) v1(60.2,40.81) v1(60.19,38.27) v1(60.2,29.38) v1(60.19,26.84) v1(60.2,25.57) v1(60.2,21.76) v1(60.2,17.95) v1(60.2,14.14) v1(60.26,54.78) v1(61.47,45.89) v1(61.47,42.08) v1(61.47,38.27) v1(61.47,32) v1(61.47,26.84) v1(61.47,23.03) v1(61.47,19.22) v1(61.47,11.6) v1(62.16,17.31) v1(63.31,49.44) v1(64,25.57) v1(64.01,24.3) v1(64.07,16.68) v1(65.21,56.07) v1(65.27,50.97) v1(65.27,42.08) v1(65.27,35.73) v1(65.28,28.11) v1(65.28,17.95) v1(65.27,12.87) v1(66.67,30.71) v1(66.67,29.44) v1(66.67,28.11) v1(71.69,17.37) v1(72.83,17.37)
DVDD_3P3: length 18.7
  TOP w0.203: U13.8 28.25,50.2 v1(28,49.95)
  TOP w0.229: v1(28.13,7.24) 28.54,7.66 U10.8 ; v1(28.25,25.54) 28.25,25.84 28.48,26.07 U11.8 ; v1(27.49,31.54) 27.72,31.77 27.92,31.77 27.94,31.79 U12.8
  TOP w0.508: R28.2 v1(19.86,30.2) ; v1(65.28,10.33) 65.36,10.33 65.37,10.32 C83.1 ; v1(64.01,11.6) 63.87,11.46 C79.1 63.18,12.49 C77.1 ; R53.2 v1(21.9,50.08)
  BOTTOM w0.254: v1(9.84,54.23) 10.28,54.67 U4.4
  BOTTOM w0.508: v1(41.33,25.79) R43.1 ; P8.C39 v1(65.28,10.33) ; R2.1 v1(45.65,30.9) ; 41.72,5.07 E1.2 ; E1.2 42.52,5.84 ; E1.2 40.92,5.84 ; R68.1 45.65,6.44 v1(45.6,6.38) ; v1(41.33,50.68) R45.1 ; P8.D38 v1(64.01,11.6) ; P8.D40 v1(64.01,9.06)
  vias: v1(11.33,53.5) v1(12.02,54.12) v1(41.21,4.66) v1(42.22,4.66)
